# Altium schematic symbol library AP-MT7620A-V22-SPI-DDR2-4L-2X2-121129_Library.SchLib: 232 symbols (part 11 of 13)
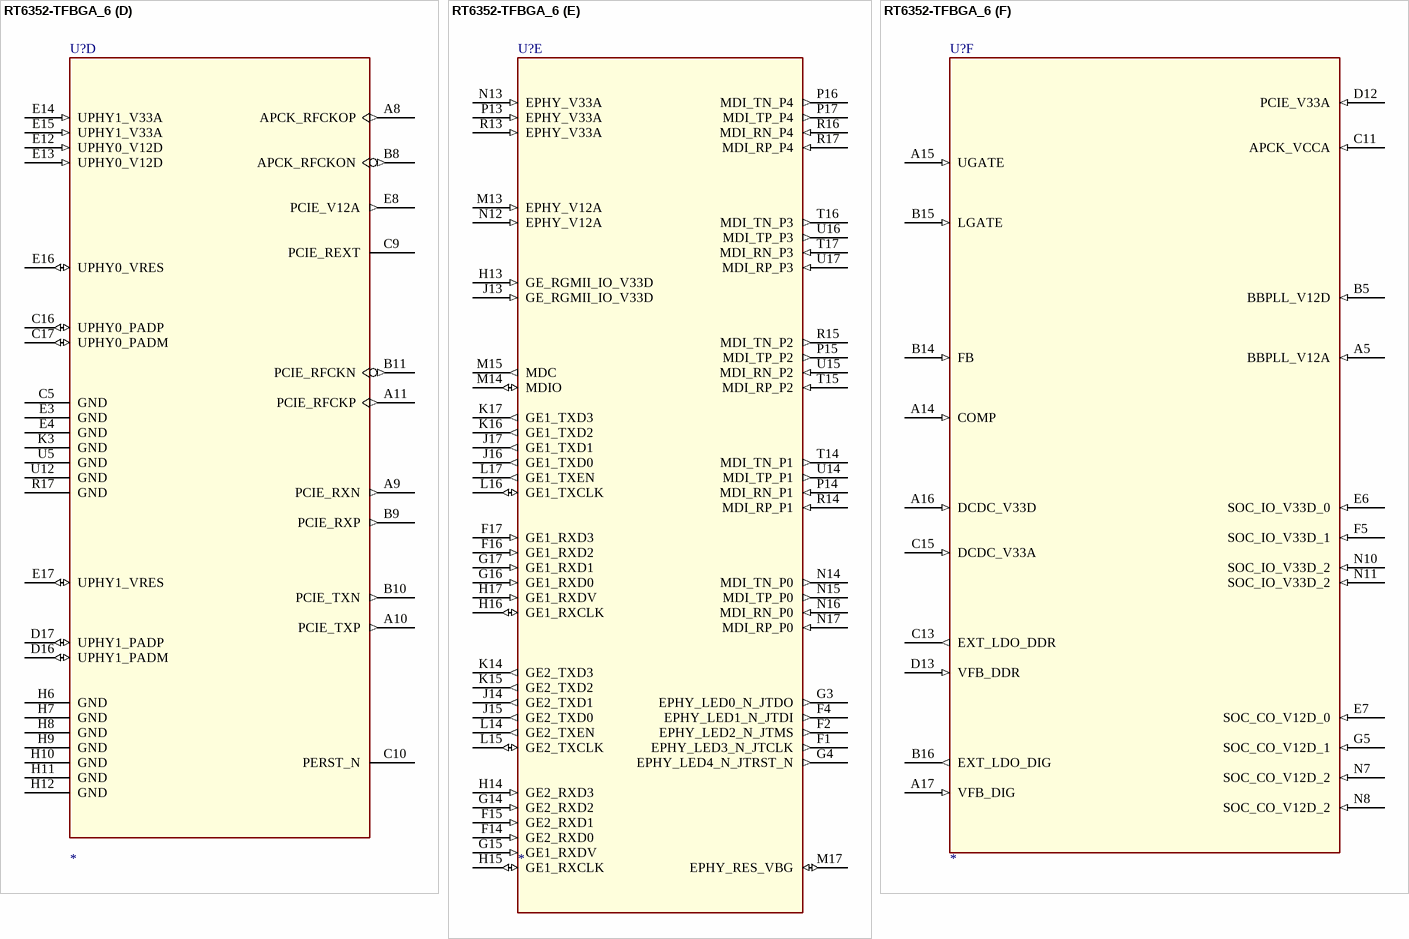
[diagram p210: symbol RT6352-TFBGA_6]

## RT6352-TFBGA_6
designator U?
footprint RT6352/BGA289/P0.65/12X12
part A pins: A1 RF0_PA2_V33P (in), A2 RF0_OUTP (out), A3 PLL_VC_CAP (out), A4 XTAL_XO (out), A6 ANT_TRN (out), B1 RF0_PA2_V33N (in), B2 RF0_OUTN (out), B3 PLL_VX_LDO, B4 XTAL_XI (out), B6 ANT_TRNB (out), C1 RF0_PA1_V33A (in), C2 RF1_VX_LDO, C3 RF0_VX_LDO, C4 XTAL_V12A (out), C6 PA_PE_G0 (out), D1 RF1_PA2_V33P (in), D2 RF1_PA2_V33N (in), D3 RF1_PA1_V33A (in), D4 BG_EXTR (out), D5 BG_V33A, D6 PA_PE_G1 (out), E1 RF1_OUTP (out), E2 RF1_OUTN (out), F3 WLED_N (out)
part B pins: F6 GND (power), F7 GND (power), F8 GND (power), F9 GND (power), F10 GND (power), F11 GND (power), F12 GND (power), G1 MD14 / MD15 (io), G2 MD9 / MD14 (io), G6 GND (power), G7 GND (power), G8 GND (power), G9 GND (power), G10 GND (power), G11 GND (power), G12 GND (power), H1 MD12 / MD13 (io), H2 MD11 / MD12 (io), H3 MRAS_N / MA5 (io), H4 MODT / MA4 (io), H5 DDR_IO_V18D/DDR_IO_V25D (in), J1 MD10 / MD11 (io), J2 MD13 / MD10 (io), J3 MCAS_N / MA7 (io), J4 MCS_N / MA6 (io), J5 DDR_IO_V18D/DDR_IO_V25D (in), K1 MD8 / MD9 (io), K2 MD15 / MD8 (io), K3 MA0 / MA8 (io), K4 MA2 / MA9 (io), K5 DDR_IOC_V12D (in), L1 MDQS1 (in), L2 MDQM1 (io), L3 MA6 / MA12 (io), L4 MA4 / MA11 (io), L5 DDR_IOC_V12D (in), M1 MCK_N (io), M2 MCK_P (io), M3 MA8 / MCKE (io), M5 MA11 / MODT (io), N1 MD5 / MD0 (io), N2 MD2 / MD1 (io), N3 MA9 / MA3 (io), N4 DDR_IO_VREF (in), N5 DDR_IO_V18D/DDR_IO_V25D (in), N6 DDR_IO_V18D/DDR_IO_V25D (in), P1 MD0 / MD2 (io), P2 MD7 / MD3 (io), P3 MA12 / MA2 (io), P4 MA7 / MA1 (io), P5 DDR_IO_VREF (in), R1 MD6 /MD4 (io), R2 MD1 / MD5 (io), R3 MA5 / MA0 (io), R4 MA3 / MA10 (io), T1 MD4 / MD6 (io), T2 MD3 / MD7 (io), T3 MA1 / MBA1 (io), T4 MBA0 / MCS_N (io), T5 MWE_N / MCAS_N (io), U1 MDQS0 (io), U2 MDQM0 (io), U3 MA10 / MBA0 (io), U4 MBA1 / MRAS_N (io), U5 MCKE / MWE_N (io)
part C pins: A7 SPI_CS0 (out), B7 SPI_CS1 (out), B17 PORST_N (in), C7 WDT_RST_N (out), C8 SPI_HOLD (out), D7 GPIO0 (io), D8 SPI_WP (out), D9 SPI_MISO (in), D10 SPI_MOSI (out), D11 SPI_CLK (out), J6 GND (power), J7 GND (power), J8 GND (power), J9 GND (power), J10 GND (power), J11 GND (power), J12 GND (power), K6 GND (power), K7 GND (power), K8 GND (power), K9 GND (power), K10 GND (power), K11 GND (power), K12 GND (power), L6 GND (power), L7 GND (power), L8 GND (power), L9 GND (power), L10 GND (power), L11 GND (power), L12 GND (power), M6 GND (power), M7 GND (power), M8 GND (power), M9 GND (power), M10 GND (power), M11 GND (power), M12 GND (power), P6 TXD2 (out), P7 RTS_N (out), P8 ND_D3/SD_D3 (out), P9 ND_D2/SD_D2 (out), P10 ND_D1/SD_D1 (out), P11 DSR_N (io), P12 RXD (io), R6 RXD2 (in), R7 ND_D5/bt_aux (out), R8 ND_CS_N (out), R9 ND_WP/SD_WP (out), R10 ND_D0/SD_D0 (out), R11 DCD_N (io), R12 RIN (io), T6 I2C_SD (out), T7 ND_D6/bt_wact (out), T8 ND_CLE/SD_card_detect, T9 ND_WE_N (out), T10 ND_ALE/SD_CMD (out), T11 TXD (out), T12 CTS_N (io), U6 I2C_SCLK (io), U7 ND_D7/bt_ant (out), U8 ND_D4/bt_stat (out), U9 ND_RE_N (out), U10 ND_RB_N/SD_CLK (out), U11 DTR_N (out)
part D pins: A8 APCK_RFCKOP (out), A9 PCIE_RXN (out), A10 PCIE_TXP (out), A11 PCIE_RFCKP (out), B8 APCK_RFCKON (out), B9 PCIE_RXP (out), B10 PCIE_TXN (out), B11 PCIE_RFCKN (out), C5 GND (power), C9 PCIE_REXT, C10 PERST_N, C16 UPHY0_PADP (io), C17 UPHY0_PADM (io), D16 UPHY1_PADM (io), D17 UPHY1_PADP (io), E3 GND (power), E4 GND (power), E8 PCIE_V12A (out), E12 UPHY0_V12D (in), E13 UPHY0_V12D (in), E14 UPHY1_V33A (in), E15 UPHY1_V33A (in), E16 UPHY0_VRES (io), E17 UPHY1_VRES (io), H6 GND (power), H7 GND (power), H8 GND (power), H9 GND (power), H10 GND (power), H11 GND (power), H12 GND (power), K3 GND (power), R17 GND (power), U5 GND (power), U12 GND (power)
part E pins: F1 EPHY_LED3_N_JTCLK (out), F2 EPHY_LED2_N_JTMS (out), F4 EPHY_LED1_N_JTDI (out), F14 GE2_RXD0 (in), F15 GE2_RXD1 (in), F16 GE1_RXD2 (in), F17 GE1_RXD3 (in), G3 EPHY_LED0_N_JTDO (out), G4 EPHY_LED4_N_JTRST_N (out), G14 GE2_RXD2 (in), G15 GE1_RXDV (in), G16 GE1_RXD0 (in), G17 GE1_RXD1 (in), H13 GE_RGMII_IO_V33D (in), H14 GE2_RXD3 (in), H15 GE1_RXCLK (io), H16 GE1_RXCLK (io), H17 GE1_RXDV (in), J13 GE_RGMII_IO_V33D (in), J14 GE2_TXD1 (out), J15 GE2_TXD0 (out), J16 GE1_TXD0 (out), J17 GE1_TXD1 (out), K14 GE2_TXD3 (out), K15 GE2_TXD2 (out), K16 GE1_TXD2 (out), K17 GE1_TXD3 (out), L14 GE2_TXEN (out), L15 GE2_TXCLK (io), L16 GE1_TXCLK (io), L17 GE1_TXEN (out), M13 EPHY_V12A (in), M14 MDIO (io), M15 MDC (out), M17 EPHY_RES_VBG (io), N12 EPHY_V12A (in), N13 EPHY_V33A (in), N14 MDI_TN_P0 (out), N15 MDI_TP_P0 (out), N16 MDI_RN_P0 (in), N17 MDI_RP_P0 (in), P13 EPHY_V33A (in), P14 MDI_RN_P1 (in), P15 MDI_TP_P2 (out), P16 MDI_TN_P4 (out), P17 MDI_TP_P4 (out), R13 EPHY_V33A (in), R14 MDI_RP_P1 (in), R15 MDI_TN_P2 (out), R16 MDI_RN_P4 (in), R17 MDI_RP_P4 (in), T14 MDI_TN_P1 (out), T15 MDI_RP_P2 (in), T16 MDI_TN_P3 (out), T17 MDI_RN_P3 (in), U14 MDI_TP_P1 (out), U15 MDI_RN_P2 (in), U16 MDI_TP_P3 (out), U17 MDI_RP_P3 (in)
part F pins: A5 BBPLL_V12A (in), A14 COMP (in), A15 UGATE (in), A16 DCDC_V33D (in), A17 VFB_DIG (in), B5 BBPLL_V12D (in), B14 FB (in), B15 LGATE (in), B16 EXT_LDO_DIG (out), C11 APCK_VCCA (in), C13 EXT_LDO_DDR (out), C15 DCDC_V33A (in), D12 PCIE_V33A (in), D13 VFB_DDR (in), E6 SOC_IO_V33D_0 (in), E7 SOC_CO_V12D_0 (in), F5 SOC_IO_V33D_1 (in), G5 SOC_CO_V12D_1 (in), N7 SOC_CO_V12D_2 (in), N8 SOC_CO_V12D_2 (in), N10 SOC_IO_V33D_2 (in), N11 SOC_IO_V33D_2 (in)

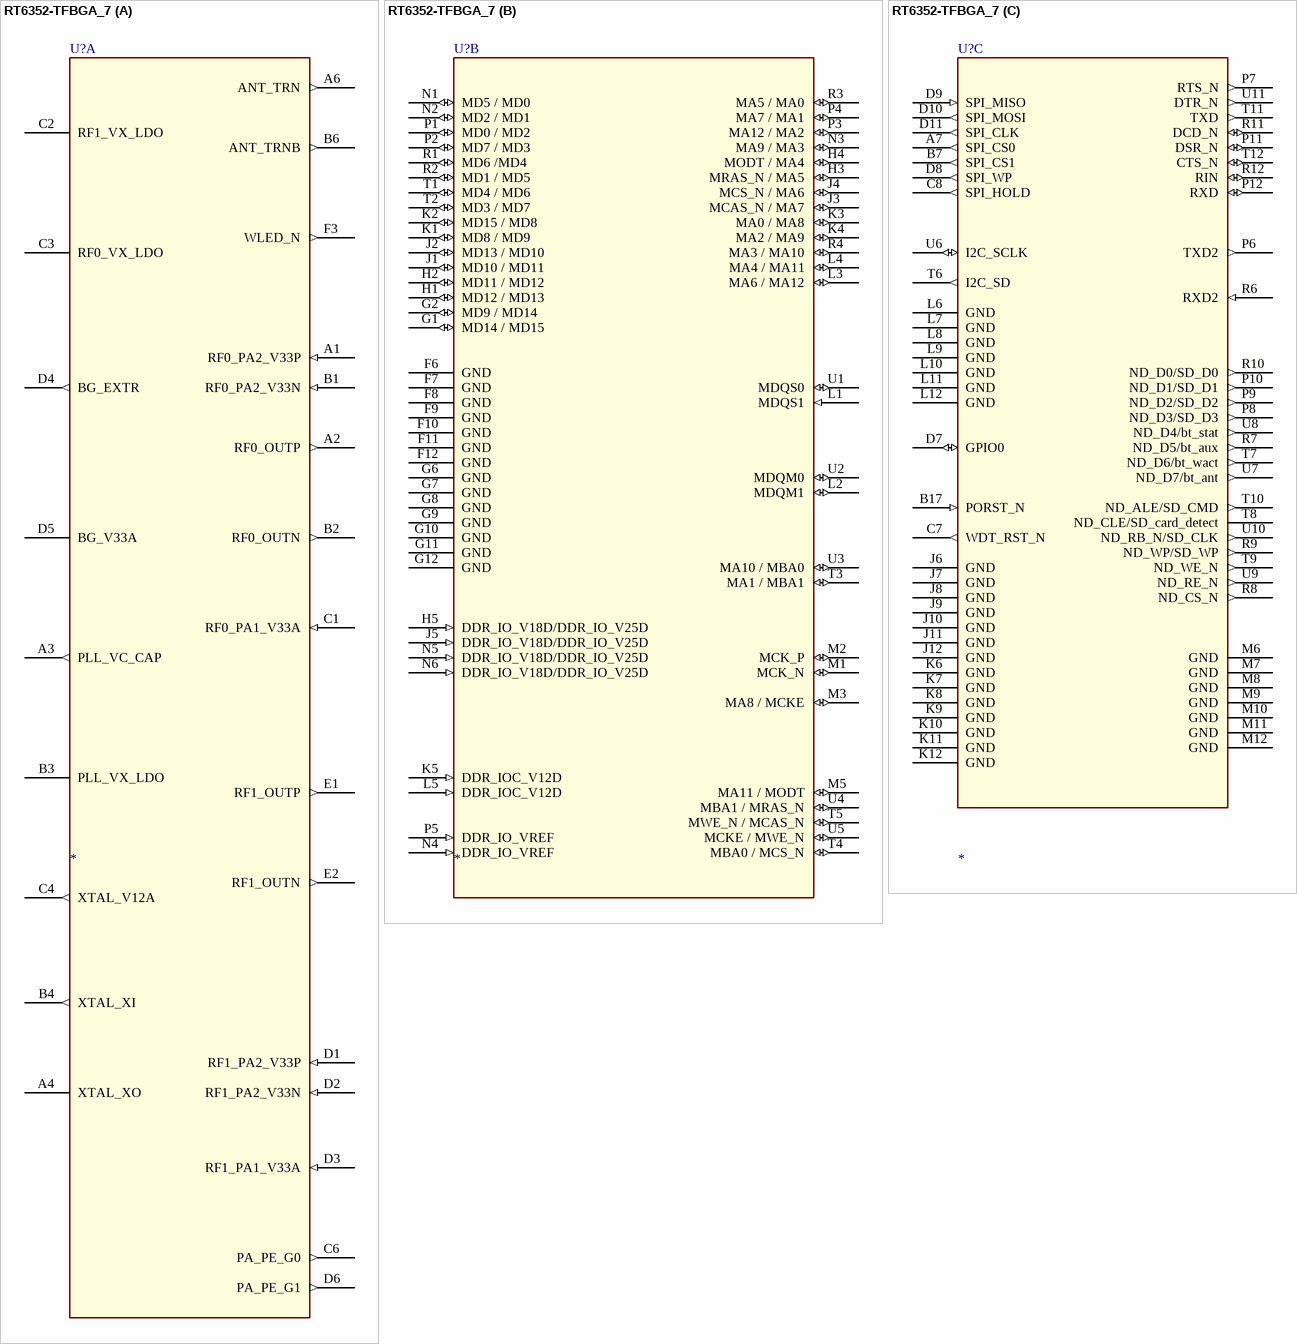
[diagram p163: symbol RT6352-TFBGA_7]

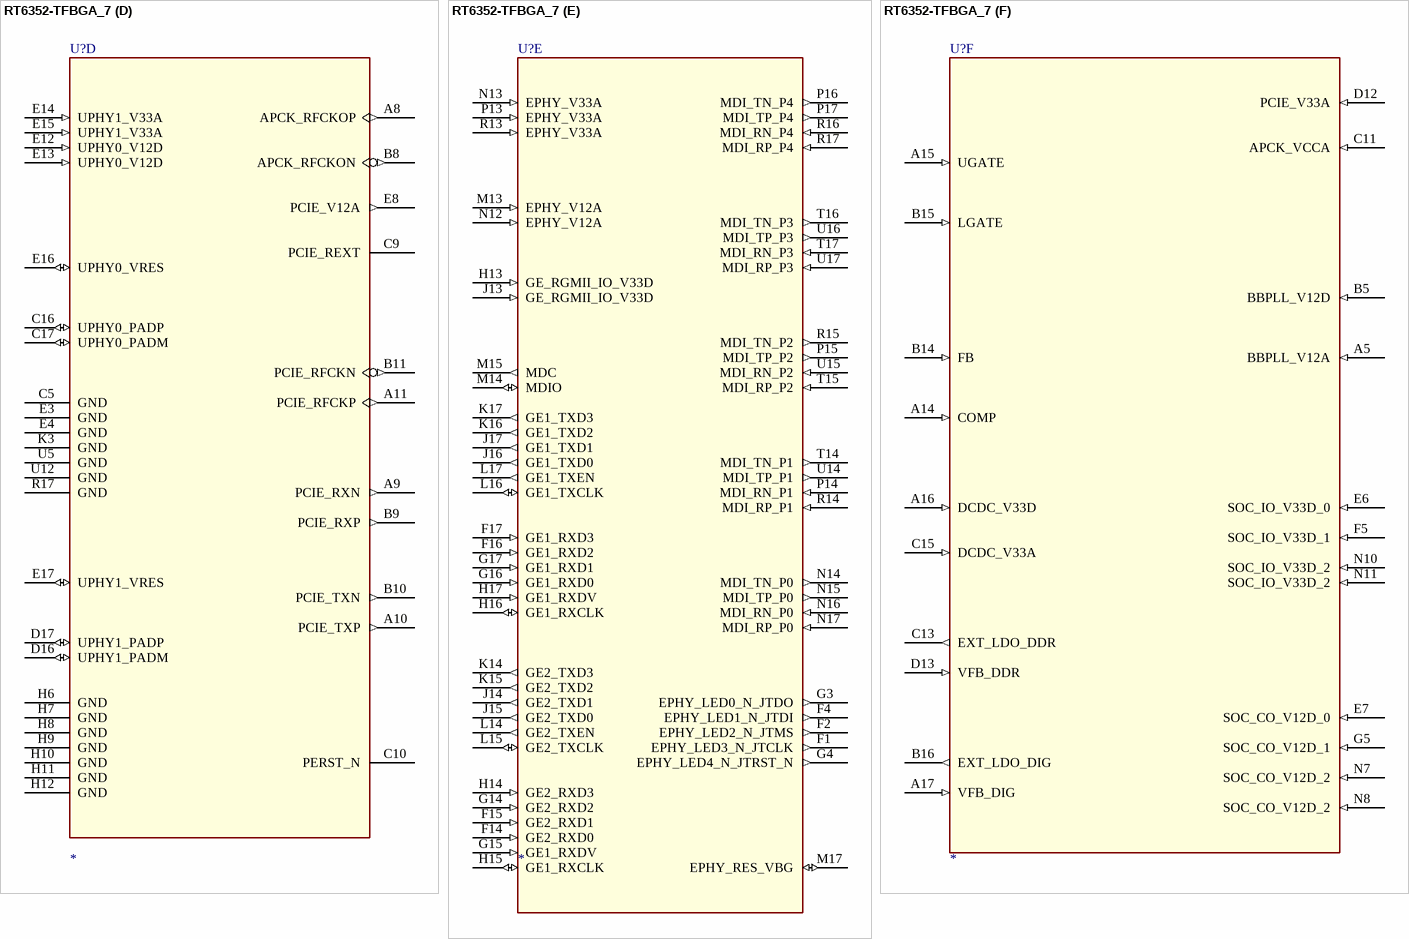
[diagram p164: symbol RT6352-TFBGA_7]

## RT6352-TFBGA_7
designator U?
footprint RT6352/BGA289/P0.65/12X12
part A pins: A1 RF0_PA2_V33P (in), A2 RF0_OUTP (out), A3 PLL_VC_CAP (out), A4 XTAL_XO, A6 ANT_TRN (out), B1 RF0_PA2_V33N (in), B2 RF0_OUTN (out), B3 PLL_VX_LDO, B4 XTAL_XI (out), B6 ANT_TRNB (out), C1 RF0_PA1_V33A (in), C2 RF1_VX_LDO, C3 RF0_VX_LDO, C4 XTAL_V12A (out), C6 PA_PE_G0 (out), D1 RF1_PA2_V33P (in), D2 RF1_PA2_V33N (in), D3 RF1_PA1_V33A (in), D4 BG_EXTR (out), D5 BG_V33A, D6 PA_PE_G1 (out), E1 RF1_OUTP (out), E2 RF1_OUTN (out), F3 WLED_N (out)
part B pins: F6 GND (power), F7 GND (power), F8 GND (power), F9 GND (power), F10 GND (power), F11 GND (power), F12 GND (power), G1 MD14 / MD15 (io), G2 MD9 / MD14 (io), G6 GND (power), G7 GND (power), G8 GND (power), G9 GND (power), G10 GND (power), G11 GND (power), G12 GND (power), H1 MD12 / MD13 (io), H2 MD11 / MD12 (io), H3 MRAS_N / MA5 (io), H4 MODT / MA4 (io), H5 DDR_IO_V18D/DDR_IO_V25D (in), J1 MD10 / MD11 (io), J2 MD13 / MD10 (io), J3 MCAS_N / MA7 (io), J4 MCS_N / MA6 (io), J5 DDR_IO_V18D/DDR_IO_V25D (in), K1 MD8 / MD9 (io), K2 MD15 / MD8 (io), K3 MA0 / MA8 (io), K4 MA2 / MA9 (io), K5 DDR_IOC_V12D (in), L1 MDQS1 (in), L2 MDQM1 (io), L3 MA6 / MA12 (io), L4 MA4 / MA11 (io), L5 DDR_IOC_V12D (in), M1 MCK_N (io), M2 MCK_P (io), M3 MA8 / MCKE (io), M5 MA11 / MODT (io), N1 MD5 / MD0 (io), N2 MD2 / MD1 (io), N3 MA9 / MA3 (io), N4 DDR_IO_VREF (in), N5 DDR_IO_V18D/DDR_IO_V25D (in), N6 DDR_IO_V18D/DDR_IO_V25D (in), P1 MD0 / MD2 (io), P2 MD7 / MD3 (io), P3 MA12 / MA2 (io), P4 MA7 / MA1 (io), P5 DDR_IO_VREF (in), R1 MD6 /MD4 (io), R2 MD1 / MD5 (io), R3 MA5 / MA0 (io), R4 MA3 / MA10 (io), T1 MD4 / MD6 (io), T2 MD3 / MD7 (io), T3 MA1 / MBA1 (io), T4 MBA0 / MCS_N (io), T5 MWE_N / MCAS_N (io), U1 MDQS0 (io), U2 MDQM0 (io), U3 MA10 / MBA0 (io), U4 MBA1 / MRAS_N (io), U5 MCKE / MWE_N (io)
part C pins: A7 SPI_CS0 (out), B7 SPI_CS1 (out), B17 PORST_N (in), C7 WDT_RST_N (out), C8 SPI_HOLD (out), D7 GPIO0 (io), D8 SPI_WP (out), D9 SPI_MISO (in), D10 SPI_MOSI (out), D11 SPI_CLK (out), J6 GND (power), J7 GND (power), J8 GND (power), J9 GND (power), J10 GND (power), J11 GND (power), J12 GND (power), K6 GND (power), K7 GND (power), K8 GND (power), K9 GND (power), K10 GND (power), K11 GND (power), K12 GND (power), L6 GND (power), L7 GND (power), L8 GND (power), L9 GND (power), L10 GND (power), L11 GND (power), L12 GND (power), M6 GND (power), M7 GND (power), M8 GND (power), M9 GND (power), M10 GND (power), M11 GND (power), M12 GND (power), P6 TXD2 (out), P7 RTS_N (out), P8 ND_D3/SD_D3 (out), P9 ND_D2/SD_D2 (out), P10 ND_D1/SD_D1 (out), P11 DSR_N (io), P12 RXD (io), R6 RXD2 (in), R7 ND_D5/bt_aux (out), R8 ND_CS_N (out), R9 ND_WP/SD_WP (out), R10 ND_D0/SD_D0 (out), R11 DCD_N (io), R12 RIN (io), T6 I2C_SD (out), T7 ND_D6/bt_wact (out), T8 ND_CLE/SD_card_detect, T9 ND_WE_N (out), T10 ND_ALE/SD_CMD (out), T11 TXD (out), T12 CTS_N (io), U6 I2C_SCLK (io), U7 ND_D7/bt_ant (out), U8 ND_D4/bt_stat (out), U9 ND_RE_N (out), U10 ND_RB_N/SD_CLK (out), U11 DTR_N (out)
part D pins: A8 APCK_RFCKOP (out), A9 PCIE_RXN (out), A10 PCIE_TXP (out), A11 PCIE_RFCKP (out), B8 APCK_RFCKON (out), B9 PCIE_RXP (out), B10 PCIE_TXN (out), B11 PCIE_RFCKN (out), C5 GND (power), C9 PCIE_REXT, C10 PERST_N, C16 UPHY0_PADP (io), C17 UPHY0_PADM (io), D16 UPHY1_PADM (io), D17 UPHY1_PADP (io), E3 GND (power), E4 GND (power), E8 PCIE_V12A (out), E12 UPHY0_V12D (in), E13 UPHY0_V12D (in), E14 UPHY1_V33A (in), E15 UPHY1_V33A (in), E16 UPHY0_VRES (io), E17 UPHY1_VRES (io), H6 GND (power), H7 GND (power), H8 GND (power), H9 GND (power), H10 GND (power), H11 GND (power), H12 GND (power), K3 GND (power), R17 GND (power), U5 GND (power), U12 GND (power)
part E pins: F1 EPHY_LED3_N_JTCLK (out), F2 EPHY_LED2_N_JTMS (out), F4 EPHY_LED1_N_JTDI (out), F14 GE2_RXD0 (in), F15 GE2_RXD1 (in), F16 GE1_RXD2 (in), F17 GE1_RXD3 (in), G3 EPHY_LED0_N_JTDO (out), G4 EPHY_LED4_N_JTRST_N (out), G14 GE2_RXD2 (in), G15 GE1_RXDV (in), G16 GE1_RXD0 (in), G17 GE1_RXD1 (in), H13 GE_RGMII_IO_V33D (in), H14 GE2_RXD3 (in), H15 GE1_RXCLK (io), H16 GE1_RXCLK (io), H17 GE1_RXDV (in), J13 GE_RGMII_IO_V33D (in), J14 GE2_TXD1 (out), J15 GE2_TXD0 (out), J16 GE1_TXD0 (out), J17 GE1_TXD1 (out), K14 GE2_TXD3 (out), K15 GE2_TXD2 (out), K16 GE1_TXD2 (out), K17 GE1_TXD3 (out), L14 GE2_TXEN (out), L15 GE2_TXCLK (io), L16 GE1_TXCLK (io), L17 GE1_TXEN (out), M13 EPHY_V12A (in), M14 MDIO (io), M15 MDC (out), M17 EPHY_RES_VBG (io), N12 EPHY_V12A (in), N13 EPHY_V33A (in), N14 MDI_TN_P0 (out), N15 MDI_TP_P0 (out), N16 MDI_RN_P0 (in), N17 MDI_RP_P0 (in), P13 EPHY_V33A (in), P14 MDI_RN_P1 (in), P15 MDI_TP_P2 (out), P16 MDI_TN_P4 (out), P17 MDI_TP_P4 (out), R13 EPHY_V33A (in), R14 MDI_RP_P1 (in), R15 MDI_TN_P2 (out), R16 MDI_RN_P4 (in), R17 MDI_RP_P4 (in), T14 MDI_TN_P1 (out), T15 MDI_RP_P2 (in), T16 MDI_TN_P3 (out), T17 MDI_RN_P3 (in), U14 MDI_TP_P1 (out), U15 MDI_RN_P2 (in), U16 MDI_TP_P3 (out), U17 MDI_RP_P3 (in)
part F pins: A5 BBPLL_V12A (in), A14 COMP (in), A15 UGATE (in), A16 DCDC_V33D (in), A17 VFB_DIG (in), B5 BBPLL_V12D (in), B14 FB (in), B15 LGATE (in), B16 EXT_LDO_DIG (out), C11 APCK_VCCA (in), C13 EXT_LDO_DDR (out), C15 DCDC_V33A (in), D12 PCIE_V33A (in), D13 VFB_DDR (in), E6 SOC_IO_V33D_0 (in), E7 SOC_CO_V12D_0 (in), F5 SOC_IO_V33D_1 (in), G5 SOC_CO_V12D_1 (in), N7 SOC_CO_V12D_2 (in), N8 SOC_CO_V12D_2 (in), N10 SOC_IO_V33D_2 (in), N11 SOC_IO_V33D_2 (in)

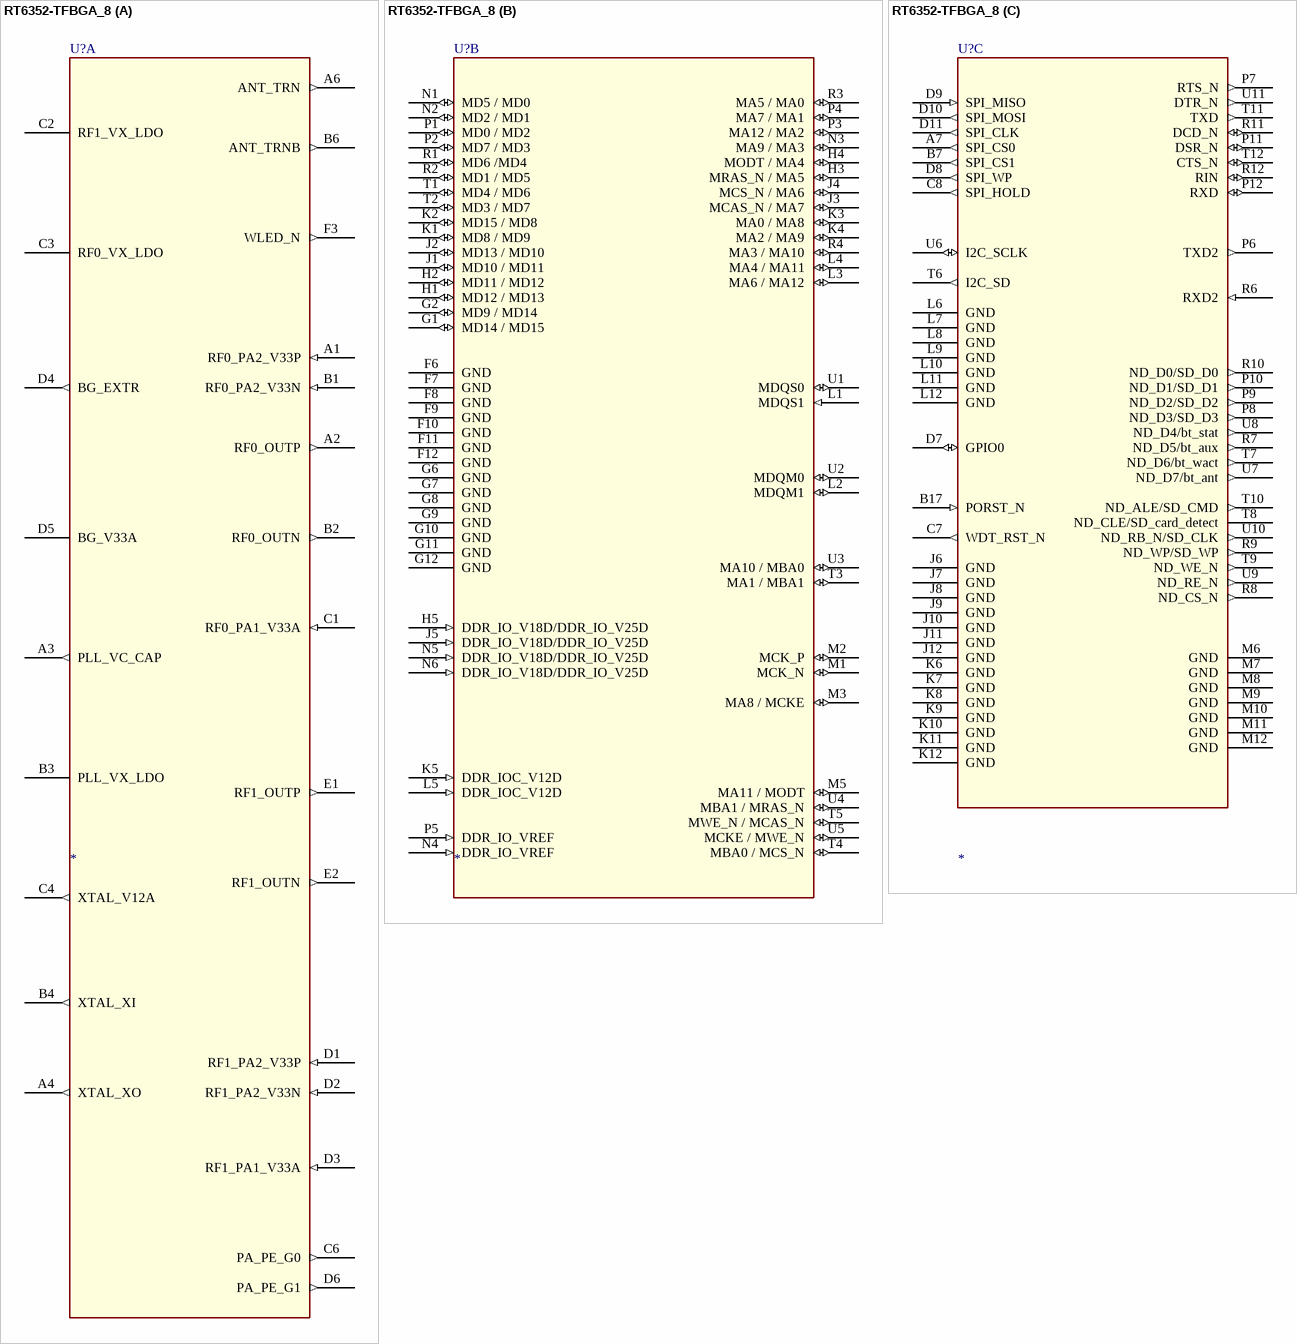
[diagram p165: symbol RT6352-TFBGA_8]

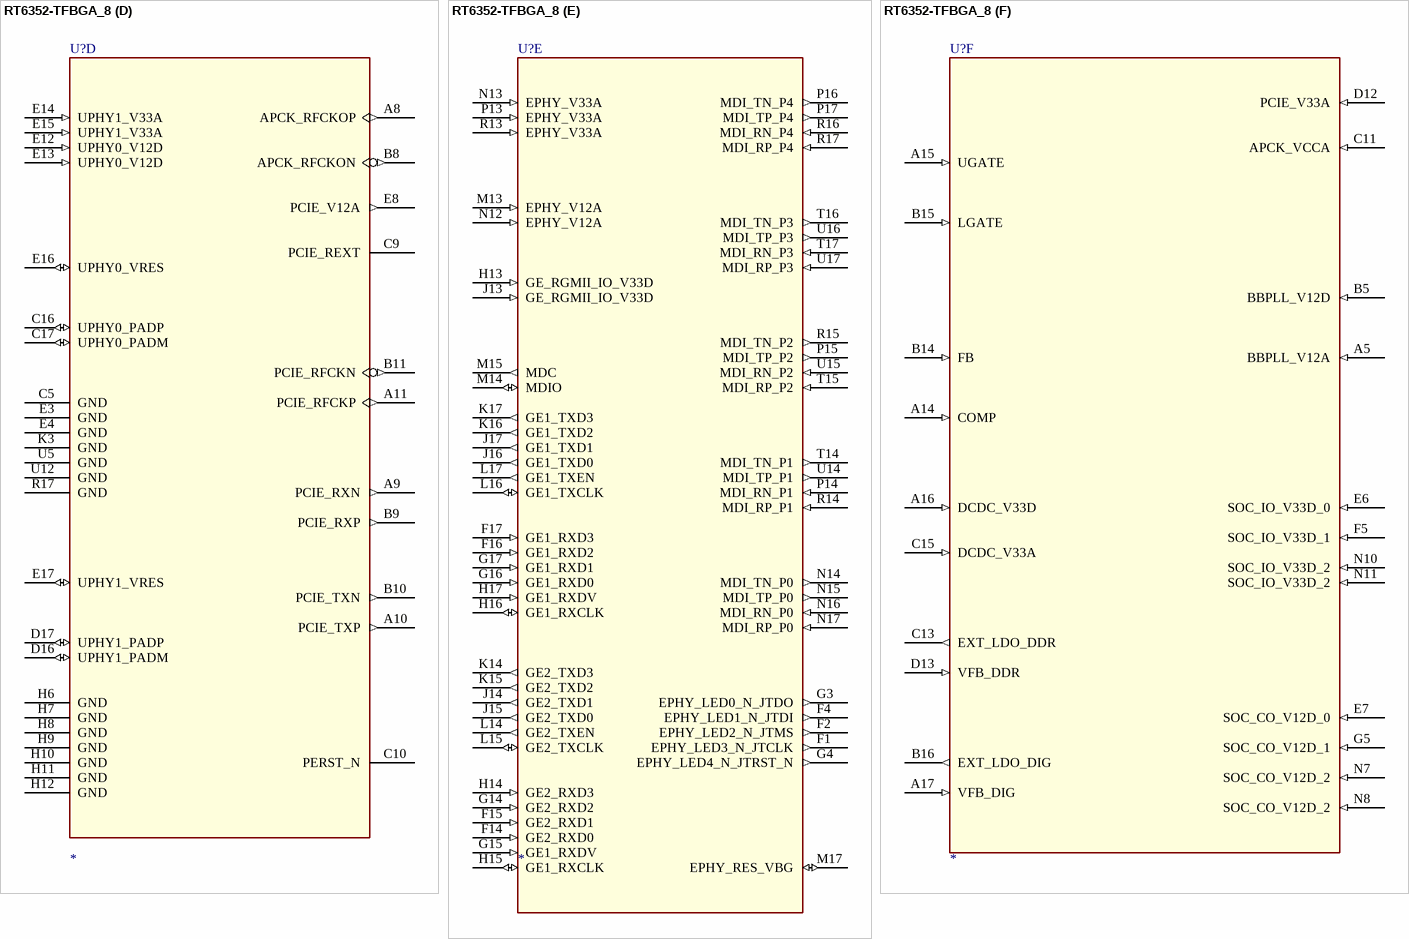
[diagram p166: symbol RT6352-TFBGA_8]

## RT6352-TFBGA_8
designator U?
footprint RT6352/BGA289/P0.65/12X12
part A pins: A1 RF0_PA2_V33P (in), A2 RF0_OUTP (out), A3 PLL_VC_CAP (out), A4 XTAL_XO (out), A6 ANT_TRN (out), B1 RF0_PA2_V33N (in), B2 RF0_OUTN (out), B3 PLL_VX_LDO, B4 XTAL_XI (out), B6 ANT_TRNB (out), C1 RF0_PA1_V33A (in), C2 RF1_VX_LDO, C3 RF0_VX_LDO, C4 XTAL_V12A (out), C6 PA_PE_G0 (out), D1 RF1_PA2_V33P (in), D2 RF1_PA2_V33N (in), D3 RF1_PA1_V33A (in), D4 BG_EXTR (out), D5 BG_V33A, D6 PA_PE_G1 (out), E1 RF1_OUTP (out), E2 RF1_OUTN (out), F3 WLED_N (out)
part B pins: F6 GND (power), F7 GND (power), F8 GND (power), F9 GND (power), F10 GND (power), F11 GND (power), F12 GND (power), G1 MD14 / MD15 (io), G2 MD9 / MD14 (io), G6 GND (power), G7 GND (power), G8 GND (power), G9 GND (power), G10 GND (power), G11 GND (power), G12 GND (power), H1 MD12 / MD13 (io), H2 MD11 / MD12 (io), H3 MRAS_N / MA5 (io), H4 MODT / MA4 (io), H5 DDR_IO_V18D/DDR_IO_V25D (in), J1 MD10 / MD11 (io), J2 MD13 / MD10 (io), J3 MCAS_N / MA7 (io), J4 MCS_N / MA6 (io), J5 DDR_IO_V18D/DDR_IO_V25D (in), K1 MD8 / MD9 (io), K2 MD15 / MD8 (io), K3 MA0 / MA8 (io), K4 MA2 / MA9 (io), K5 DDR_IOC_V12D (in), L1 MDQS1 (in), L2 MDQM1 (io), L3 MA6 / MA12 (io), L4 MA4 / MA11 (io), L5 DDR_IOC_V12D (in), M1 MCK_N (io), M2 MCK_P (io), M3 MA8 / MCKE (io), M5 MA11 / MODT (io), N1 MD5 / MD0 (io), N2 MD2 / MD1 (io), N3 MA9 / MA3 (io), N4 DDR_IO_VREF (in), N5 DDR_IO_V18D/DDR_IO_V25D (in), N6 DDR_IO_V18D/DDR_IO_V25D (in), P1 MD0 / MD2 (io), P2 MD7 / MD3 (io), P3 MA12 / MA2 (io), P4 MA7 / MA1 (io), P5 DDR_IO_VREF (in), R1 MD6 /MD4 (io), R2 MD1 / MD5 (io), R3 MA5 / MA0 (io), R4 MA3 / MA10 (io), T1 MD4 / MD6 (io), T2 MD3 / MD7 (io), T3 MA1 / MBA1 (io), T4 MBA0 / MCS_N (io), T5 MWE_N / MCAS_N (io), U1 MDQS0 (io), U2 MDQM0 (io), U3 MA10 / MBA0 (io), U4 MBA1 / MRAS_N (io), U5 MCKE / MWE_N (io)
part C pins: A7 SPI_CS0 (out), B7 SPI_CS1 (out), B17 PORST_N (in), C7 WDT_RST_N (out), C8 SPI_HOLD (out), D7 GPIO0 (io), D8 SPI_WP (out), D9 SPI_MISO (in), D10 SPI_MOSI (out), D11 SPI_CLK (out), J6 GND (power), J7 GND (power), J8 GND (power), J9 GND (power), J10 GND (power), J11 GND (power), J12 GND (power), K6 GND (power), K7 GND (power), K8 GND (power), K9 GND (power), K10 GND (power), K11 GND (power), K12 GND (power), L6 GND (power), L7 GND (power), L8 GND (power), L9 GND (power), L10 GND (power), L11 GND (power), L12 GND (power), M6 GND (power), M7 GND (power), M8 GND (power), M9 GND (power), M10 GND (power), M11 GND (power), M12 GND (power), P6 TXD2 (out), P7 RTS_N (out), P8 ND_D3/SD_D3 (out), P9 ND_D2/SD_D2 (out), P10 ND_D1/SD_D1 (out), P11 DSR_N (io), P12 RXD (io), R6 RXD2 (in), R7 ND_D5/bt_aux (out), R8 ND_CS_N (out), R9 ND_WP/SD_WP (out), R10 ND_D0/SD_D0 (out), R11 DCD_N (io), R12 RIN (io), T6 I2C_SD (out), T7 ND_D6/bt_wact (out), T8 ND_CLE/SD_card_detect, T9 ND_WE_N (out), T10 ND_ALE/SD_CMD (out), T11 TXD (out), T12 CTS_N (io), U6 I2C_SCLK (io), U7 ND_D7/bt_ant (out), U8 ND_D4/bt_stat (out), U9 ND_RE_N (out), U10 ND_RB_N/SD_CLK (out), U11 DTR_N (out)
part D pins: A8 APCK_RFCKOP (out), A9 PCIE_RXN (out), A10 PCIE_TXP (out), A11 PCIE_RFCKP (out), B8 APCK_RFCKON (out), B9 PCIE_RXP (out), B10 PCIE_TXN (out), B11 PCIE_RFCKN (out), C5 GND (power), C9 PCIE_REXT, C10 PERST_N, C16 UPHY0_PADP (io), C17 UPHY0_PADM (io), D16 UPHY1_PADM (io), D17 UPHY1_PADP (io), E3 GND (power), E4 GND (power), E8 PCIE_V12A (out), E12 UPHY0_V12D (in), E13 UPHY0_V12D (in), E14 UPHY1_V33A (in), E15 UPHY1_V33A (in), E16 UPHY0_VRES (io), E17 UPHY1_VRES (io), H6 GND (power), H7 GND (power), H8 GND (power), H9 GND (power), H10 GND (power), H11 GND (power), H12 GND (power), K3 GND (power), R17 GND (power), U5 GND (power), U12 GND (power)
part E pins: F1 EPHY_LED3_N_JTCLK (out), F2 EPHY_LED2_N_JTMS (out), F4 EPHY_LED1_N_JTDI (out), F14 GE2_RXD0 (in), F15 GE2_RXD1 (in), F16 GE1_RXD2 (in), F17 GE1_RXD3 (in), G3 EPHY_LED0_N_JTDO (out), G4 EPHY_LED4_N_JTRST_N (out), G14 GE2_RXD2 (in), G15 GE1_RXDV (in), G16 GE1_RXD0 (in), G17 GE1_RXD1 (in), H13 GE_RGMII_IO_V33D (in), H14 GE2_RXD3 (in), H15 GE1_RXCLK (io), H16 GE1_RXCLK (io), H17 GE1_RXDV (in), J13 GE_RGMII_IO_V33D (in), J14 GE2_TXD1 (out), J15 GE2_TXD0 (out), J16 GE1_TXD0 (out), J17 GE1_TXD1 (out), K14 GE2_TXD3 (out), K15 GE2_TXD2 (out), K16 GE1_TXD2 (out), K17 GE1_TXD3 (out), L14 GE2_TXEN (out), L15 GE2_TXCLK (io), L16 GE1_TXCLK (io), L17 GE1_TXEN (out), M13 EPHY_V12A (in), M14 MDIO (io), M15 MDC (out), M17 EPHY_RES_VBG (io), N12 EPHY_V12A (in), N13 EPHY_V33A (in), N14 MDI_TN_P0 (out), N15 MDI_TP_P0 (out), N16 MDI_RN_P0 (in), N17 MDI_RP_P0 (in), P13 EPHY_V33A (in), P14 MDI_RN_P1 (in), P15 MDI_TP_P2 (out), P16 MDI_TN_P4 (out), P17 MDI_TP_P4 (out), R13 EPHY_V33A (in), R14 MDI_RP_P1 (in), R15 MDI_TN_P2 (out), R16 MDI_RN_P4 (in), R17 MDI_RP_P4 (in), T14 MDI_TN_P1 (out), T15 MDI_RP_P2 (in), T16 MDI_TN_P3 (out), T17 MDI_RN_P3 (in), U14 MDI_TP_P1 (out), U15 MDI_RN_P2 (in), U16 MDI_TP_P3 (out), U17 MDI_RP_P3 (in)
part F pins: A5 BBPLL_V12A (in), A14 COMP (in), A15 UGATE (in), A16 DCDC_V33D (in), A17 VFB_DIG (in), B5 BBPLL_V12D (in), B14 FB (in), B15 LGATE (in), B16 EXT_LDO_DIG (out), C11 APCK_VCCA (in), C13 EXT_LDO_DDR (out), C15 DCDC_V33A (in), D12 PCIE_V33A (in), D13 VFB_DDR (in), E6 SOC_IO_V33D_0 (in), E7 SOC_CO_V12D_0 (in), F5 SOC_IO_V33D_1 (in), G5 SOC_CO_V12D_1 (in), N7 SOC_CO_V12D_2 (in), N8 SOC_CO_V12D_2 (in), N10 SOC_IO_V33D_2 (in), N11 SOC_IO_V33D_2 (in)

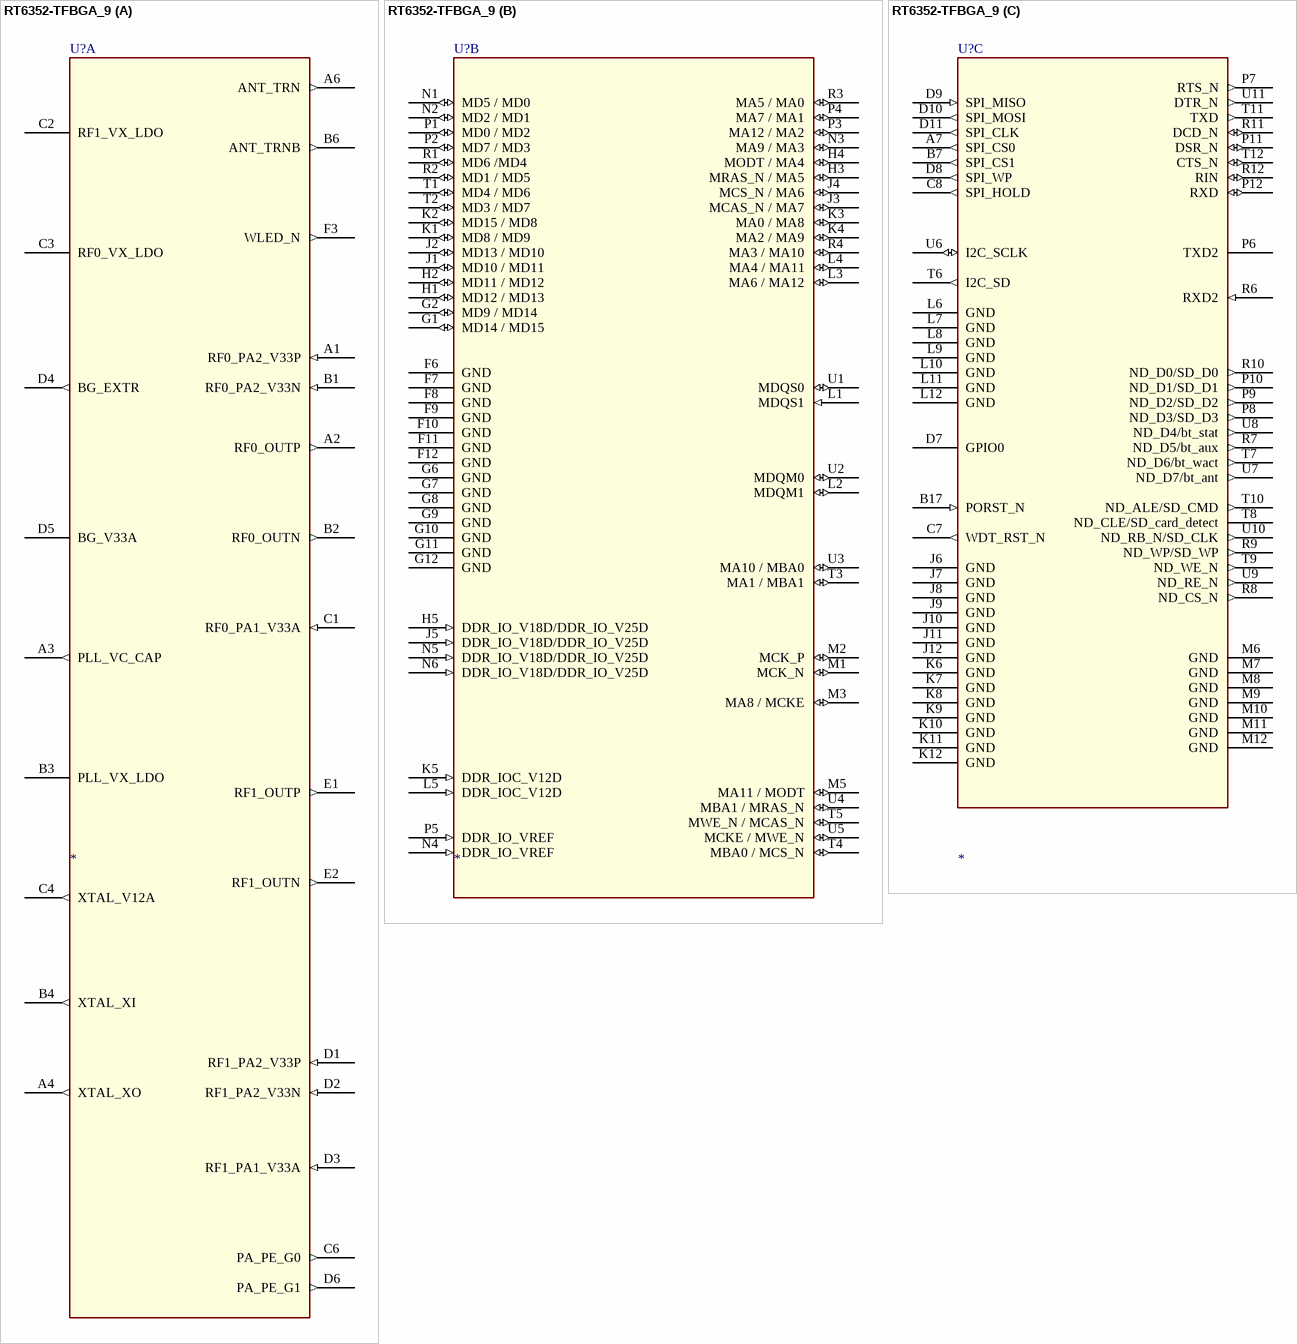
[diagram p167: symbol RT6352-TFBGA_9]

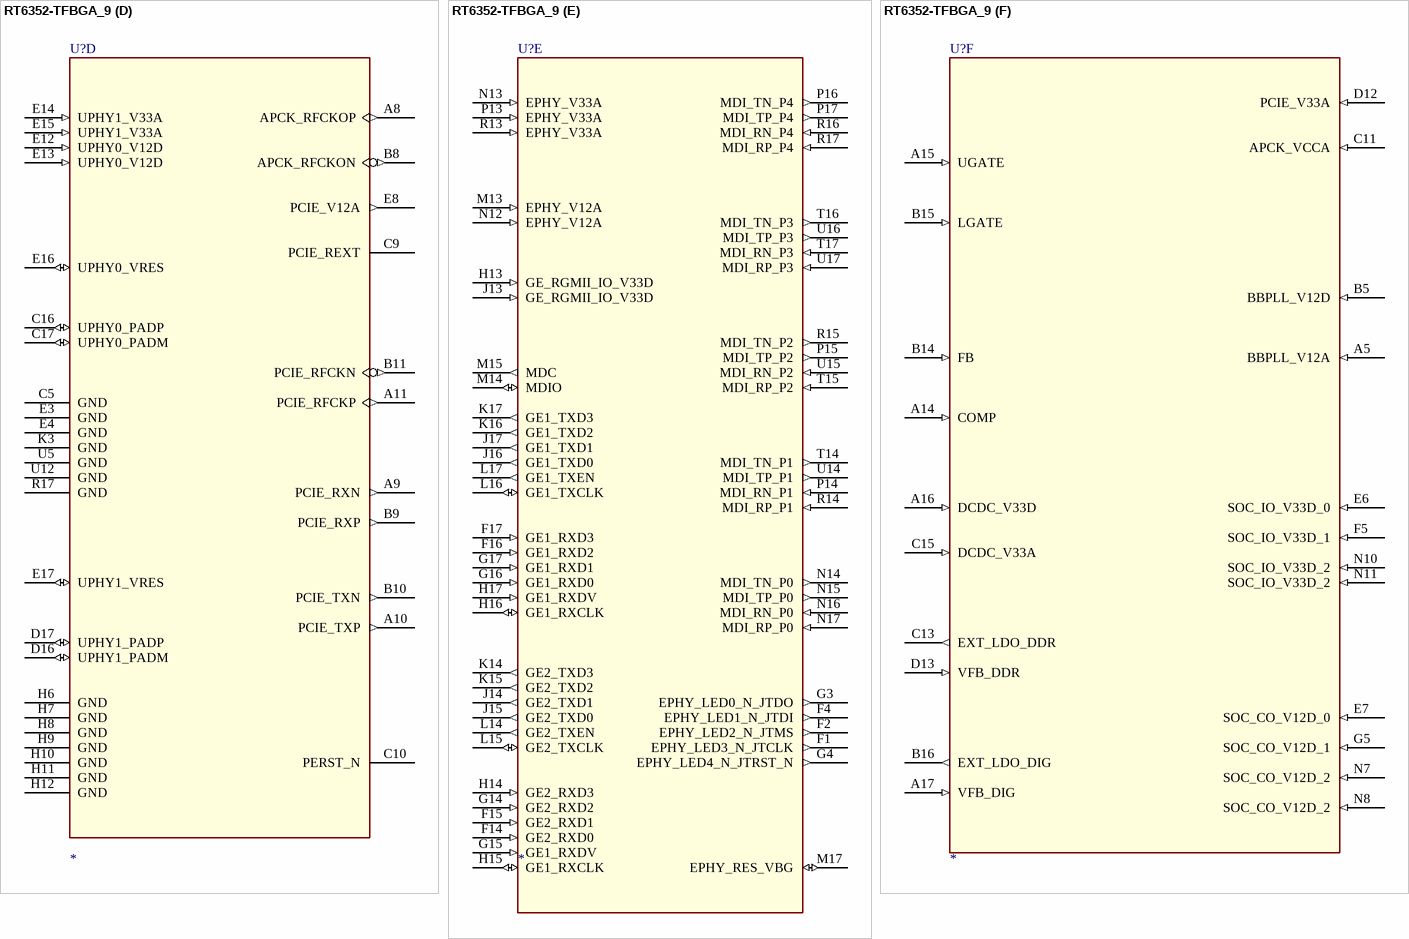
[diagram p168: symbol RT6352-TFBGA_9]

## RT6352-TFBGA_9
designator U?
footprint RT6352/BGA289/P0.65/12X12
part A pins: A1 RF0_PA2_V33P (in), A2 RF0_OUTP (out), A3 PLL_VC_CAP (out), A4 XTAL_XO (out), A6 ANT_TRN (out), B1 RF0_PA2_V33N (in), B2 RF0_OUTN (out), B3 PLL_VX_LDO, B4 XTAL_XI (out), B6 ANT_TRNB (out), C1 RF0_PA1_V33A (in), C2 RF1_VX_LDO, C3 RF0_VX_LDO, C4 XTAL_V12A (out), C6 PA_PE_G0 (out), D1 RF1_PA2_V33P (in), D2 RF1_PA2_V33N (in), D3 RF1_PA1_V33A (in), D4 BG_EXTR (out), D5 BG_V33A, D6 PA_PE_G1 (out), E1 RF1_OUTP (out), E2 RF1_OUTN (out), F3 WLED_N (out)
part B pins: F6 GND (power), F7 GND (power), F8 GND (power), F9 GND (power), F10 GND (power), F11 GND (power), F12 GND (power), G1 MD14 / MD15 (io), G2 MD9 / MD14 (io), G6 GND (power), G7 GND (power), G8 GND (power), G9 GND (power), G10 GND (power), G11 GND (power), G12 GND (power), H1 MD12 / MD13 (io), H2 MD11 / MD12 (io), H3 MRAS_N / MA5 (io), H4 MODT / MA4 (io), H5 DDR_IO_V18D/DDR_IO_V25D (in), J1 MD10 / MD11 (io), J2 MD13 / MD10 (io), J3 MCAS_N / MA7 (io), J4 MCS_N / MA6 (io), J5 DDR_IO_V18D/DDR_IO_V25D (in), K1 MD8 / MD9 (io), K2 MD15 / MD8 (io), K3 MA0 / MA8 (io), K4 MA2 / MA9 (io), K5 DDR_IOC_V12D (in), L1 MDQS1 (in), L2 MDQM1 (io), L3 MA6 / MA12 (io), L4 MA4 / MA11 (io), L5 DDR_IOC_V12D (in), M1 MCK_N (io), M2 MCK_P (io), M3 MA8 / MCKE (io), M5 MA11 / MODT (io), N1 MD5 / MD0 (io), N2 MD2 / MD1 (io), N3 MA9 / MA3 (io), N4 DDR_IO_VREF (in), N5 DDR_IO_V18D/DDR_IO_V25D (in), N6 DDR_IO_V18D/DDR_IO_V25D (in), P1 MD0 / MD2 (io), P2 MD7 / MD3 (io), P3 MA12 / MA2 (io), P4 MA7 / MA1 (io), P5 DDR_IO_VREF (in), R1 MD6 /MD4 (io), R2 MD1 / MD5 (io), R3 MA5 / MA0 (io), R4 MA3 / MA10 (io), T1 MD4 / MD6 (io), T2 MD3 / MD7 (io), T3 MA1 / MBA1 (io), T4 MBA0 / MCS_N (io), T5 MWE_N / MCAS_N (io), U1 MDQS0 (io), U2 MDQM0 (io), U3 MA10 / MBA0 (io), U4 MBA1 / MRAS_N (io), U5 MCKE / MWE_N (io)
part C pins: A7 SPI_CS0 (out), B7 SPI_CS1 (out), B17 PORST_N (in), C7 WDT_RST_N (out), C8 SPI_HOLD (out), D7 GPIO0, D8 SPI_WP (out), D9 SPI_MISO (in), D10 SPI_MOSI (out), D11 SPI_CLK (out), J6 GND (power), J7 GND (power), J8 GND (power), J9 GND (power), J10 GND (power), J11 GND (power), J12 GND (power), K6 GND (power), K7 GND (power), K8 GND (power), K9 GND (power), K10 GND (power), K11 GND (power), K12 GND (power), L6 GND (power), L7 GND (power), L8 GND (power), L9 GND (power), L10 GND (power), L11 GND (power), L12 GND (power), M6 GND (power), M7 GND (power), M8 GND (power), M9 GND (power), M10 GND (power), M11 GND (power), M12 GND (power), P6 TXD2, P7 RTS_N (out), P8 ND_D3/SD_D3 (out), P9 ND_D2/SD_D2 (out), P10 ND_D1/SD_D1 (out), P11 DSR_N (io), P12 RXD (io), R6 RXD2 (in), R7 ND_D5/bt_aux (out), R8 ND_CS_N (out), R9 ND_WP/SD_WP (out), R10 ND_D0/SD_D0 (out), R11 DCD_N (io), R12 RIN (io), T6 I2C_SD (out), T7 ND_D6/bt_wact (out), T8 ND_CLE/SD_card_detect, T9 ND_WE_N (out), T10 ND_ALE/SD_CMD (out), T11 TXD (out), T12 CTS_N (io), U6 I2C_SCLK (io), U7 ND_D7/bt_ant (out), U8 ND_D4/bt_stat (out), U9 ND_RE_N (out), U10 ND_RB_N/SD_CLK (out), U11 DTR_N (out)
part D pins: A8 APCK_RFCKOP (out), A9 PCIE_RXN (out), A10 PCIE_TXP (out), A11 PCIE_RFCKP (out), B8 APCK_RFCKON (out), B9 PCIE_RXP (out), B10 PCIE_TXN (out), B11 PCIE_RFCKN (out), C5 GND (power), C9 PCIE_REXT, C10 PERST_N, C16 UPHY0_PADP (io), C17 UPHY0_PADM (io), D16 UPHY1_PADM (io), D17 UPHY1_PADP (io), E3 GND (power), E4 GND (power), E8 PCIE_V12A (out), E12 UPHY0_V12D (in), E13 UPHY0_V12D (in), E14 UPHY1_V33A (in), E15 UPHY1_V33A (in), E16 UPHY0_VRES (io), E17 UPHY1_VRES (io), H6 GND (power), H7 GND (power), H8 GND (power), H9 GND (power), H10 GND (power), H11 GND (power), H12 GND (power), K3 GND (power), R17 GND (power), U5 GND (power), U12 GND (power)
part E pins: F1 EPHY_LED3_N_JTCLK (out), F2 EPHY_LED2_N_JTMS (out), F4 EPHY_LED1_N_JTDI (out), F14 GE2_RXD0 (in), F15 GE2_RXD1 (in), F16 GE1_RXD2 (in), F17 GE1_RXD3 (in), G3 EPHY_LED0_N_JTDO (out), G4 EPHY_LED4_N_JTRST_N (out), G14 GE2_RXD2 (in), G15 GE1_RXDV (in), G16 GE1_RXD0 (in), G17 GE1_RXD1 (in), H13 GE_RGMII_IO_V33D (in), H14 GE2_RXD3 (in), H15 GE1_RXCLK (io), H16 GE1_RXCLK (io), H17 GE1_RXDV (in), J13 GE_RGMII_IO_V33D (in), J14 GE2_TXD1 (out), J15 GE2_TXD0 (out), J16 GE1_TXD0 (out), J17 GE1_TXD1 (out), K14 GE2_TXD3 (out), K15 GE2_TXD2 (out), K16 GE1_TXD2 (out), K17 GE1_TXD3 (out), L14 GE2_TXEN (out), L15 GE2_TXCLK (io), L16 GE1_TXCLK (io), L17 GE1_TXEN (out), M13 EPHY_V12A (in), M14 MDIO (io), M15 MDC (out), M17 EPHY_RES_VBG (io), N12 EPHY_V12A (in), N13 EPHY_V33A (in), N14 MDI_TN_P0 (out), N15 MDI_TP_P0 (out), N16 MDI_RN_P0 (in), N17 MDI_RP_P0 (in), P13 EPHY_V33A (in), P14 MDI_RN_P1 (in), P15 MDI_TP_P2 (out), P16 MDI_TN_P4 (out), P17 MDI_TP_P4 (out), R13 EPHY_V33A (in), R14 MDI_RP_P1 (in), R15 MDI_TN_P2 (out), R16 MDI_RN_P4 (in), R17 MDI_RP_P4 (in), T14 MDI_TN_P1 (out), T15 MDI_RP_P2 (in), T16 MDI_TN_P3 (out), T17 MDI_RN_P3 (in), U14 MDI_TP_P1 (out), U15 MDI_RN_P2 (in), U16 MDI_TP_P3 (out), U17 MDI_RP_P3 (in)
part F pins: A5 BBPLL_V12A (in), A14 COMP (in), A15 UGATE (in), A16 DCDC_V33D (in), A17 VFB_DIG (in), B5 BBPLL_V12D (in), B14 FB (in), B15 LGATE (in), B16 EXT_LDO_DIG (out), C11 APCK_VCCA (in), C13 EXT_LDO_DDR (out), C15 DCDC_V33A (in), D12 PCIE_V33A (in), D13 VFB_DDR (in), E6 SOC_IO_V33D_0 (in), E7 SOC_CO_V12D_0 (in), F5 SOC_IO_V33D_1 (in), G5 SOC_CO_V12D_1 (in), N7 SOC_CO_V12D_2 (in), N8 SOC_CO_V12D_2 (in), N10 SOC_IO_V33D_2 (in), N11 SOC_IO_V33D_2 (in)

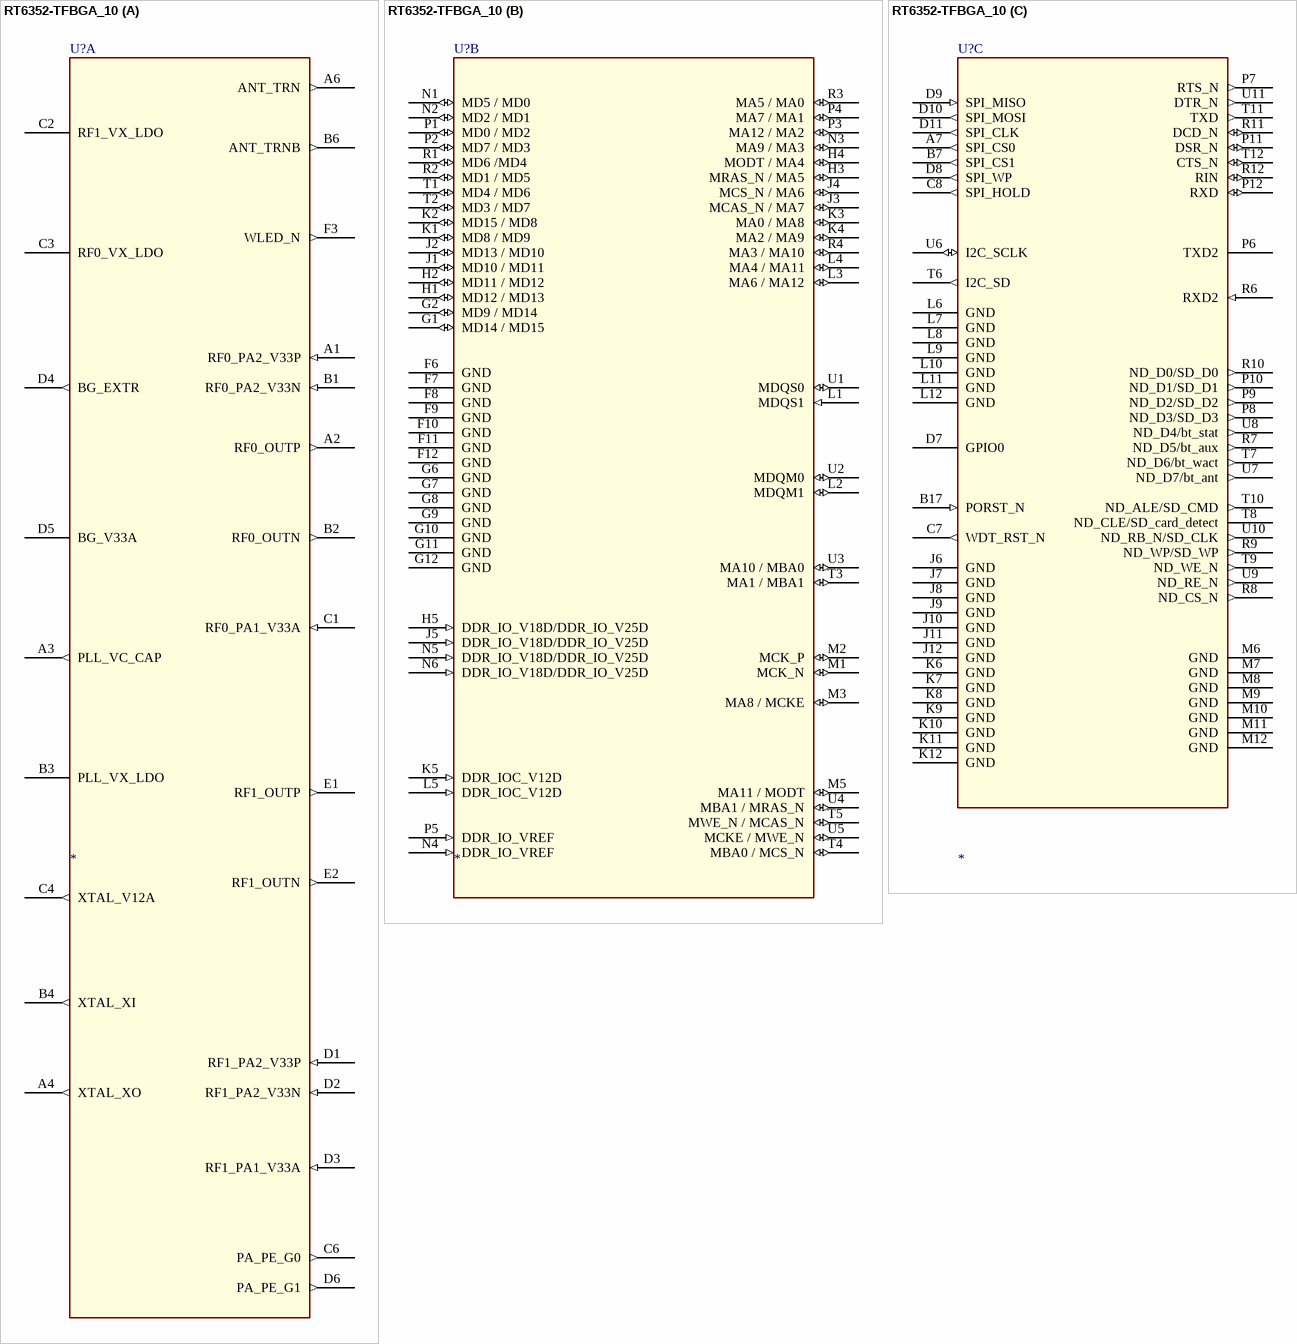
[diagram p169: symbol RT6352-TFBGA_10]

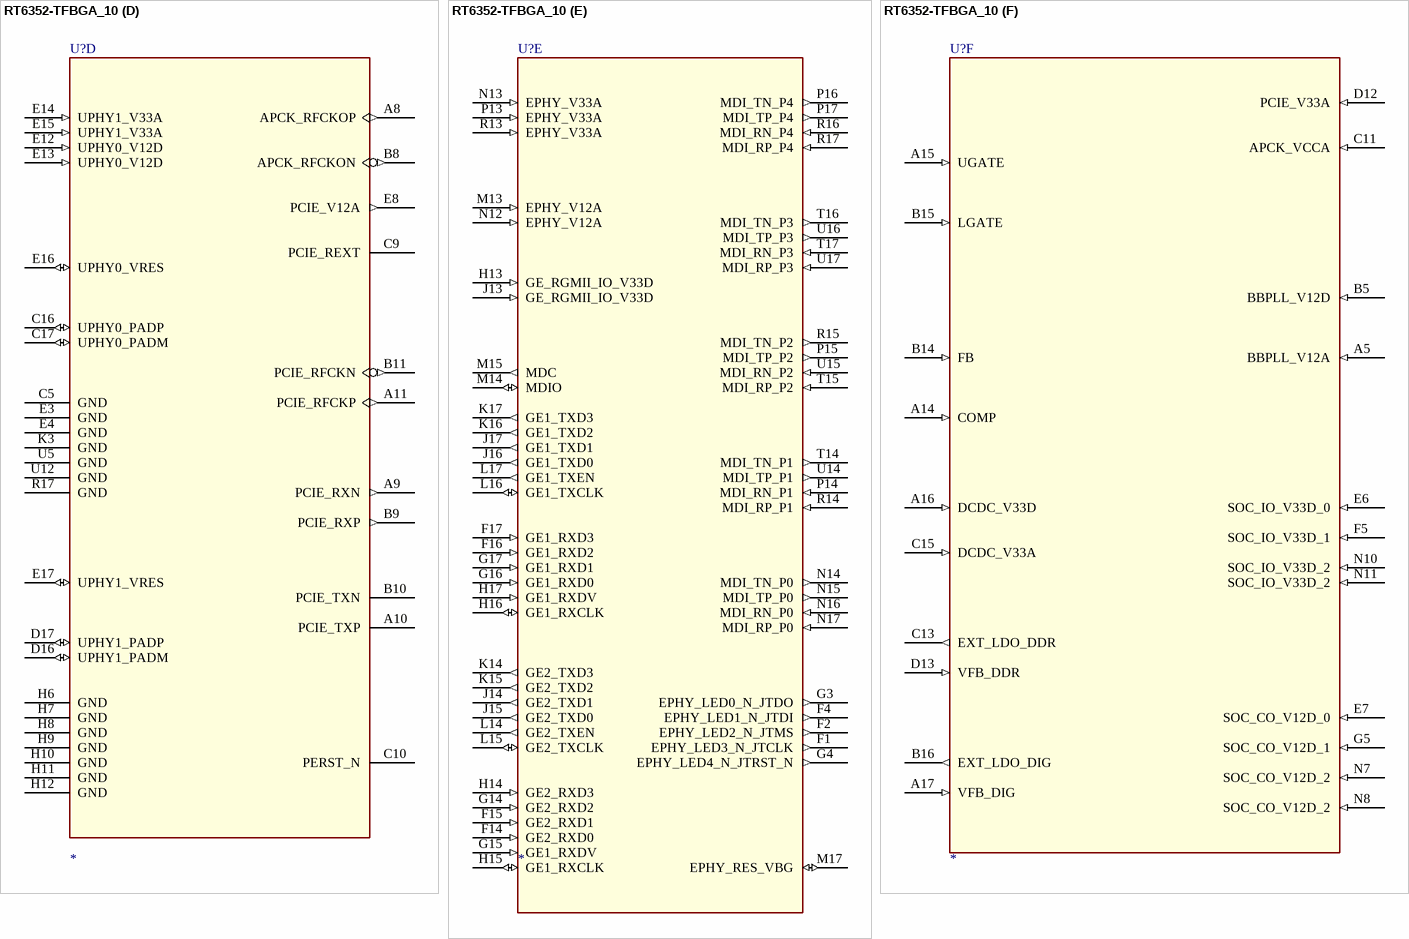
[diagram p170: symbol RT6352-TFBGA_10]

## RT6352-TFBGA_10
designator U?
footprint RT6352/BGA289/P0.65/12X12
part A pins: A1 RF0_PA2_V33P (in), A2 RF0_OUTP (out), A3 PLL_VC_CAP (out), A4 XTAL_XO (out), A6 ANT_TRN (out), B1 RF0_PA2_V33N (in), B2 RF0_OUTN (out), B3 PLL_VX_LDO, B4 XTAL_XI (out), B6 ANT_TRNB (out), C1 RF0_PA1_V33A (in), C2 RF1_VX_LDO, C3 RF0_VX_LDO, C4 XTAL_V12A (out), C6 PA_PE_G0 (out), D1 RF1_PA2_V33P (in), D2 RF1_PA2_V33N (in), D3 RF1_PA1_V33A (in), D4 BG_EXTR (out), D5 BG_V33A, D6 PA_PE_G1 (out), E1 RF1_OUTP (out), E2 RF1_OUTN (out), F3 WLED_N (out)
part B pins: F6 GND (power), F7 GND (power), F8 GND (power), F9 GND (power), F10 GND (power), F11 GND (power), F12 GND (power), G1 MD14 / MD15 (io), G2 MD9 / MD14 (io), G6 GND (power), G7 GND (power), G8 GND (power), G9 GND (power), G10 GND (power), G11 GND (power), G12 GND (power), H1 MD12 / MD13 (io), H2 MD11 / MD12 (io), H3 MRAS_N / MA5 (io), H4 MODT / MA4 (io), H5 DDR_IO_V18D/DDR_IO_V25D (in), J1 MD10 / MD11 (io), J2 MD13 / MD10 (io), J3 MCAS_N / MA7 (io), J4 MCS_N / MA6 (io), J5 DDR_IO_V18D/DDR_IO_V25D (in), K1 MD8 / MD9 (io), K2 MD15 / MD8 (io), K3 MA0 / MA8 (io), K4 MA2 / MA9 (io), K5 DDR_IOC_V12D (in), L1 MDQS1 (in), L2 MDQM1 (io), L3 MA6 / MA12 (io), L4 MA4 / MA11 (io), L5 DDR_IOC_V12D (in), M1 MCK_N (io), M2 MCK_P (io), M3 MA8 / MCKE (io), M5 MA11 / MODT (io), N1 MD5 / MD0 (io), N2 MD2 / MD1 (io), N3 MA9 / MA3 (io), N4 DDR_IO_VREF (in), N5 DDR_IO_V18D/DDR_IO_V25D (in), N6 DDR_IO_V18D/DDR_IO_V25D (in), P1 MD0 / MD2 (io), P2 MD7 / MD3 (io), P3 MA12 / MA2 (io), P4 MA7 / MA1 (io), P5 DDR_IO_VREF (in), R1 MD6 /MD4 (io), R2 MD1 / MD5 (io), R3 MA5 / MA0 (io), R4 MA3 / MA10 (io), T1 MD4 / MD6 (io), T2 MD3 / MD7 (io), T3 MA1 / MBA1 (io), T4 MBA0 / MCS_N (io), T5 MWE_N / MCAS_N (io), U1 MDQS0 (io), U2 MDQM0 (io), U3 MA10 / MBA0 (io), U4 MBA1 / MRAS_N (io), U5 MCKE / MWE_N (io)
part C pins: A7 SPI_CS0 (out), B7 SPI_CS1 (out), B17 PORST_N (in), C7 WDT_RST_N (out), C8 SPI_HOLD (out), D7 GPIO0, D8 SPI_WP (out), D9 SPI_MISO (in), D10 SPI_MOSI (out), D11 SPI_CLK (out), J6 GND (power), J7 GND (power), J8 GND (power), J9 GND (power), J10 GND (power), J11 GND (power), J12 GND (power), K6 GND (power), K7 GND (power), K8 GND (power), K9 GND (power), K10 GND (power), K11 GND (power), K12 GND (power), L6 GND (power), L7 GND (power), L8 GND (power), L9 GND (power), L10 GND (power), L11 GND (power), L12 GND (power), M6 GND (power), M7 GND (power), M8 GND (power), M9 GND (power), M10 GND (power), M11 GND (power), M12 GND (power), P6 TXD2, P7 RTS_N (out), P8 ND_D3/SD_D3 (out), P9 ND_D2/SD_D2 (out), P10 ND_D1/SD_D1 (out), P11 DSR_N (io), P12 RXD (io), R6 RXD2 (in), R7 ND_D5/bt_aux (out), R8 ND_CS_N (out), R9 ND_WP/SD_WP (out), R10 ND_D0/SD_D0 (out), R11 DCD_N (io), R12 RIN (io), T6 I2C_SD (out), T7 ND_D6/bt_wact (out), T8 ND_CLE/SD_card_detect, T9 ND_WE_N (out), T10 ND_ALE/SD_CMD (out), T11 TXD (out), T12 CTS_N (io), U6 I2C_SCLK (io), U7 ND_D7/bt_ant (out), U8 ND_D4/bt_stat (out), U9 ND_RE_N (out), U10 ND_RB_N/SD_CLK (out), U11 DTR_N (out)
part D pins: A8 APCK_RFCKOP (out), A9 PCIE_RXN (out), A10 PCIE_TXP, A11 PCIE_RFCKP (out), B8 APCK_RFCKON (out), B9 PCIE_RXP (out), B10 PCIE_TXN, B11 PCIE_RFCKN (out), C5 GND, C9 PCIE_REXT, C10 PERST_N, C16 UPHY0_PADP (io), C17 UPHY0_PADM (io), D16 UPHY1_PADM (io), D17 UPHY1_PADP (io), E3 GND, E4 GND, E8 PCIE_V12A (out), E12 UPHY0_V12D (in), E13 UPHY0_V12D (in), E14 UPHY1_V33A (in), E15 UPHY1_V33A (in), E16 UPHY0_VRES (io), E17 UPHY1_VRES (io), H6 GND (power), H7 GND (power), H8 GND (power), H9 GND (power), H10 GND (power), H11 GND (power), H12 GND (power), K3 GND, R17 GND, U5 GND, U12 GND
part E pins: F1 EPHY_LED3_N_JTCLK (out), F2 EPHY_LED2_N_JTMS (out), F4 EPHY_LED1_N_JTDI (out), F14 GE2_RXD0 (in), F15 GE2_RXD1 (in), F16 GE1_RXD2 (in), F17 GE1_RXD3 (in), G3 EPHY_LED0_N_JTDO (out), G4 EPHY_LED4_N_JTRST_N (out), G14 GE2_RXD2 (in), G15 GE1_RXDV (in), G16 GE1_RXD0 (in), G17 GE1_RXD1 (in), H13 GE_RGMII_IO_V33D (in), H14 GE2_RXD3 (in), H15 GE1_RXCLK (io), H16 GE1_RXCLK (io), H17 GE1_RXDV (in), J13 GE_RGMII_IO_V33D (in), J14 GE2_TXD1 (out), J15 GE2_TXD0 (out), J16 GE1_TXD0 (out), J17 GE1_TXD1 (out), K14 GE2_TXD3 (out), K15 GE2_TXD2 (out), K16 GE1_TXD2 (out), K17 GE1_TXD3 (out), L14 GE2_TXEN (out), L15 GE2_TXCLK (io), L16 GE1_TXCLK (io), L17 GE1_TXEN (out), M13 EPHY_V12A (in), M14 MDIO (io), M15 MDC (out), M17 EPHY_RES_VBG (io), N12 EPHY_V12A (in), N13 EPHY_V33A (in), N14 MDI_TN_P0 (out), N15 MDI_TP_P0 (out), N16 MDI_RN_P0 (in), N17 MDI_RP_P0 (in), P13 EPHY_V33A (in), P14 MDI_RN_P1 (in), P15 MDI_TP_P2 (out), P16 MDI_TN_P4 (out), P17 MDI_TP_P4 (out), R13 EPHY_V33A (in), R14 MDI_RP_P1 (in), R15 MDI_TN_P2 (out), R16 MDI_RN_P4 (in), R17 MDI_RP_P4 (in), T14 MDI_TN_P1 (out), T15 MDI_RP_P2 (in), T16 MDI_TN_P3 (out), T17 MDI_RN_P3 (in), U14 MDI_TP_P1 (out), U15 MDI_RN_P2 (in), U16 MDI_TP_P3 (out), U17 MDI_RP_P3 (in)
part F pins: A5 BBPLL_V12A (in), A14 COMP (in), A15 UGATE (in), A16 DCDC_V33D (in), A17 VFB_DIG (in), B5 BBPLL_V12D (in), B14 FB (in), B15 LGATE (in), B16 EXT_LDO_DIG (out), C11 APCK_VCCA (in), C13 EXT_LDO_DDR (out), C15 DCDC_V33A (in), D12 PCIE_V33A (in), D13 VFB_DDR (in), E6 SOC_IO_V33D_0 (in), E7 SOC_CO_V12D_0 (in), F5 SOC_IO_V33D_1 (in), G5 SOC_CO_V12D_1 (in), N7 SOC_CO_V12D_2 (in), N8 SOC_CO_V12D_2 (in), N10 SOC_IO_V33D_2 (in), N11 SOC_IO_V33D_2 (in)

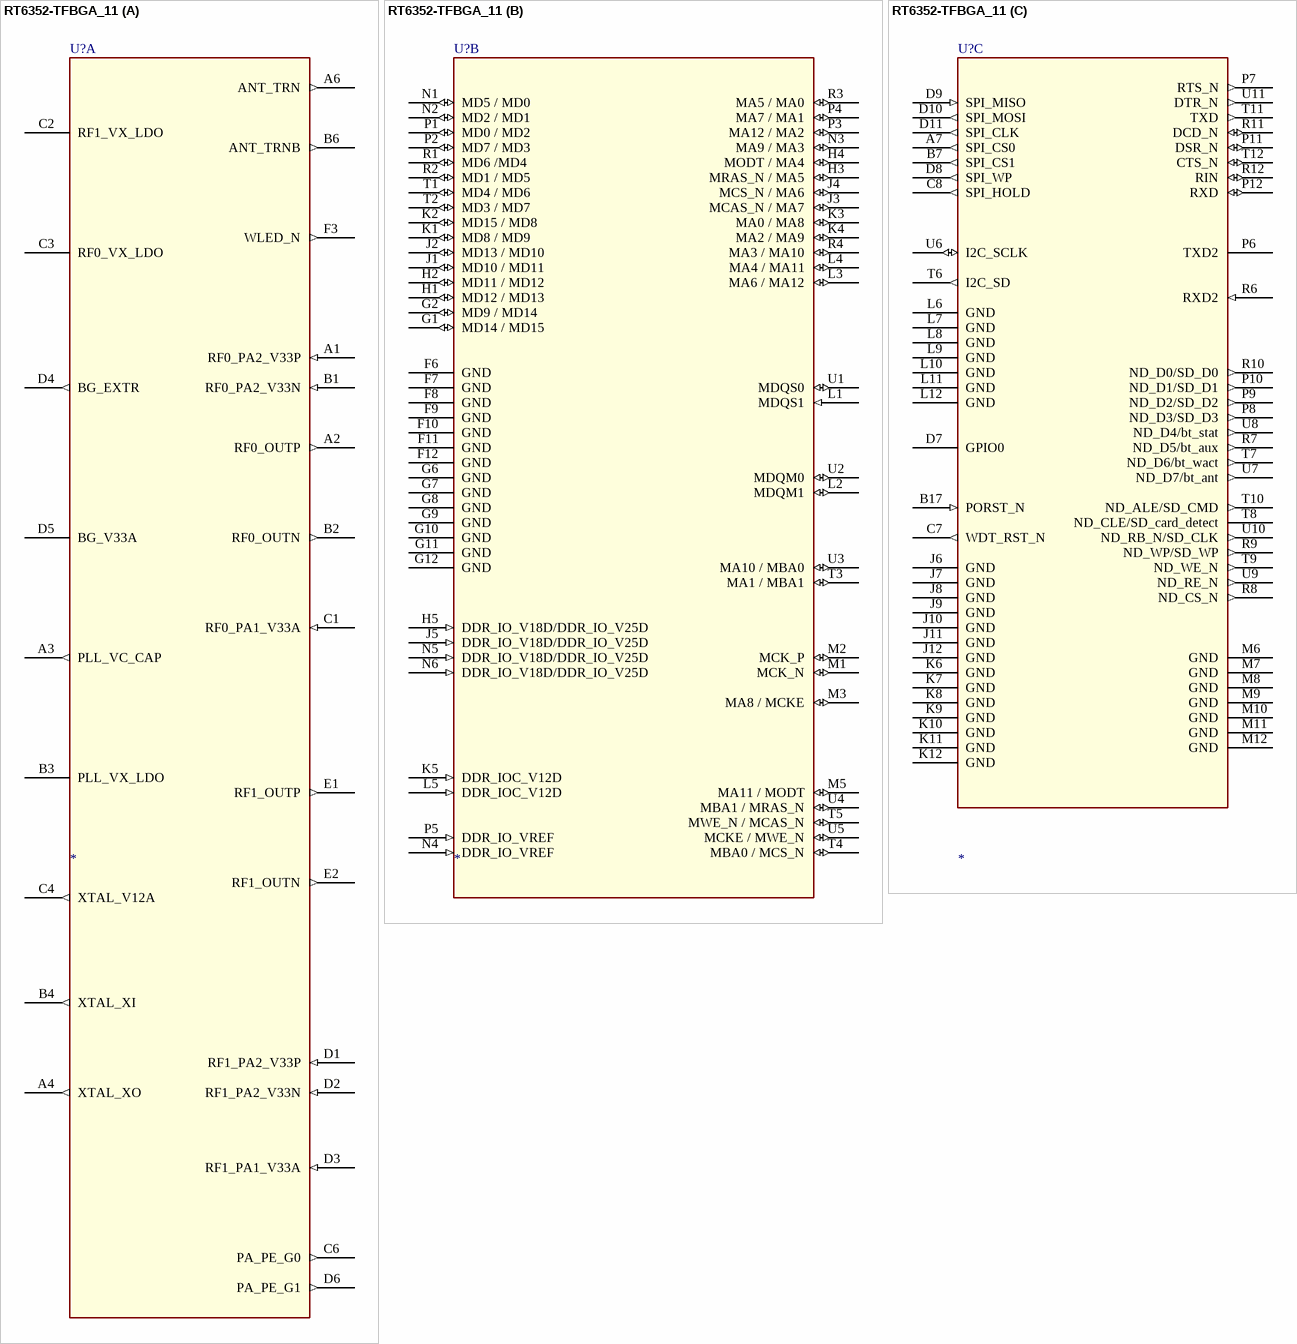
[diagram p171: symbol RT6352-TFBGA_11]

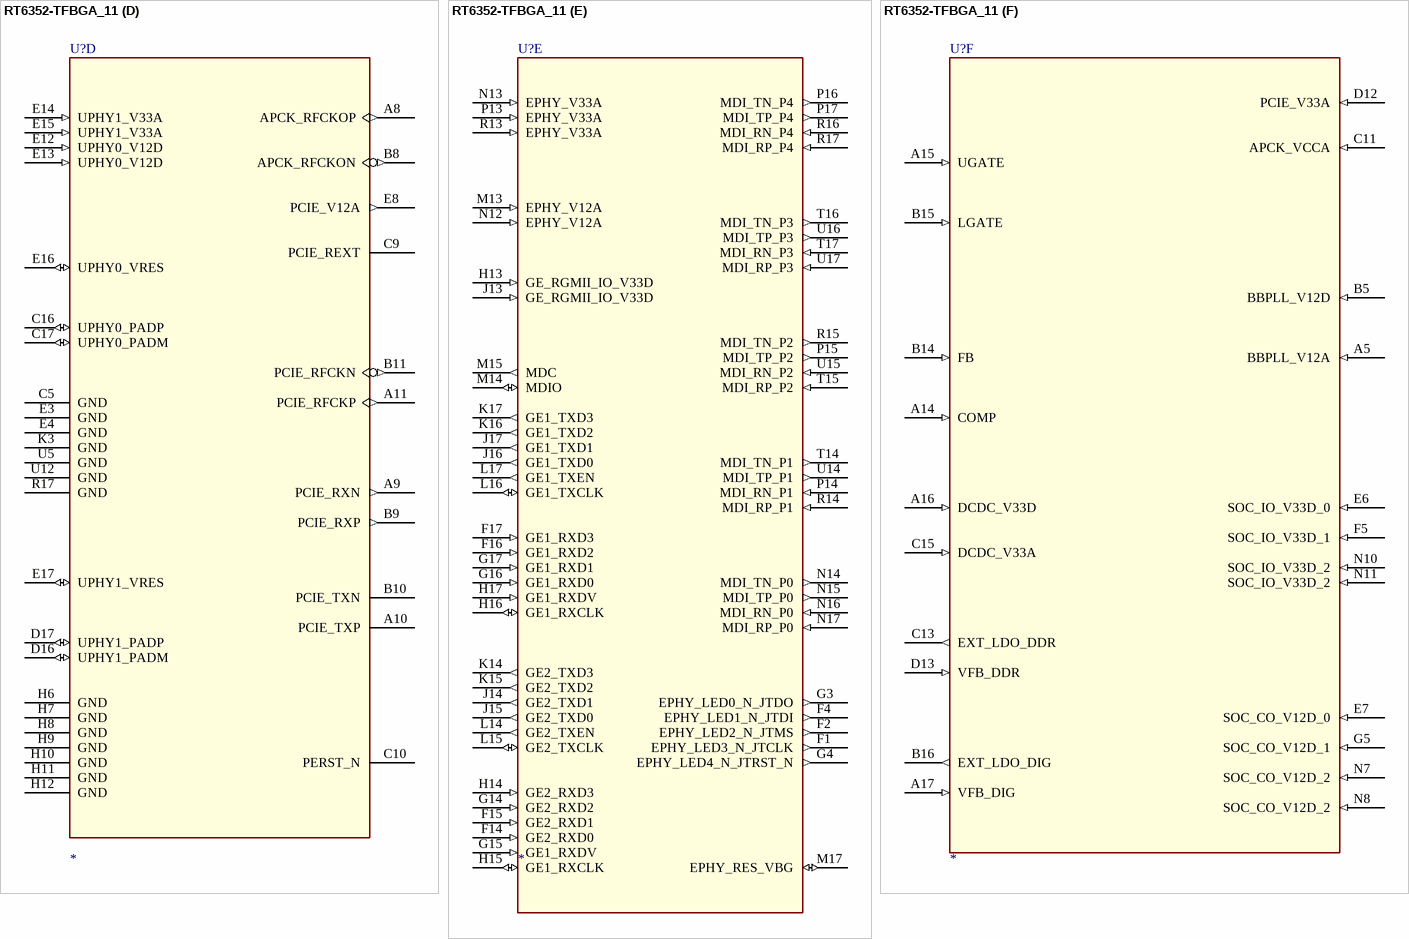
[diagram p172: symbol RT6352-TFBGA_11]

## RT6352-TFBGA_11
designator U?
footprint RT6352/BGA289/P0.65/12X12
part A pins: A1 RF0_PA2_V33P (in), A2 RF0_OUTP (out), A3 PLL_VC_CAP (out), A4 XTAL_XO (out), A6 ANT_TRN (out), B1 RF0_PA2_V33N (in), B2 RF0_OUTN (out), B3 PLL_VX_LDO, B4 XTAL_XI (out), B6 ANT_TRNB (out), C1 RF0_PA1_V33A (in), C2 RF1_VX_LDO, C3 RF0_VX_LDO, C4 XTAL_V12A (out), C6 PA_PE_G0 (out), D1 RF1_PA2_V33P (in), D2 RF1_PA2_V33N (in), D3 RF1_PA1_V33A (in), D4 BG_EXTR (out), D5 BG_V33A, D6 PA_PE_G1 (out), E1 RF1_OUTP (out), E2 RF1_OUTN (out), F3 WLED_N (out)
part B pins: F6 GND (power), F7 GND (power), F8 GND (power), F9 GND (power), F10 GND (power), F11 GND (power), F12 GND (power), G1 MD14 / MD15 (io), G2 MD9 / MD14 (io), G6 GND (power), G7 GND (power), G8 GND (power), G9 GND (power), G10 GND (power), G11 GND (power), G12 GND (power), H1 MD12 / MD13 (io), H2 MD11 / MD12 (io), H3 MRAS_N / MA5 (io), H4 MODT / MA4 (io), H5 DDR_IO_V18D/DDR_IO_V25D (in), J1 MD10 / MD11 (io), J2 MD13 / MD10 (io), J3 MCAS_N / MA7 (io), J4 MCS_N / MA6 (io), J5 DDR_IO_V18D/DDR_IO_V25D (in), K1 MD8 / MD9 (io), K2 MD15 / MD8 (io), K3 MA0 / MA8 (io), K4 MA2 / MA9 (io), K5 DDR_IOC_V12D (in), L1 MDQS1 (in), L2 MDQM1 (io), L3 MA6 / MA12 (io), L4 MA4 / MA11 (io), L5 DDR_IOC_V12D (in), M1 MCK_N (io), M2 MCK_P (io), M3 MA8 / MCKE (io), M5 MA11 / MODT (io), N1 MD5 / MD0 (io), N2 MD2 / MD1 (io), N3 MA9 / MA3 (io), N4 DDR_IO_VREF (in), N5 DDR_IO_V18D/DDR_IO_V25D (in), N6 DDR_IO_V18D/DDR_IO_V25D (in), P1 MD0 / MD2 (io), P2 MD7 / MD3 (io), P3 MA12 / MA2 (io), P4 MA7 / MA1 (io), P5 DDR_IO_VREF (in), R1 MD6 /MD4 (io), R2 MD1 / MD5 (io), R3 MA5 / MA0 (io), R4 MA3 / MA10 (io), T1 MD4 / MD6 (io), T2 MD3 / MD7 (io), T3 MA1 / MBA1 (io), T4 MBA0 / MCS_N (io), T5 MWE_N / MCAS_N (io), U1 MDQS0 (io), U2 MDQM0 (io), U3 MA10 / MBA0 (io), U4 MBA1 / MRAS_N (io), U5 MCKE / MWE_N (io)
part C pins: A7 SPI_CS0 (out), B7 SPI_CS1 (out), B17 PORST_N (in), C7 WDT_RST_N (out), C8 SPI_HOLD (out), D7 GPIO0, D8 SPI_WP (out), D9 SPI_MISO (in), D10 SPI_MOSI (out), D11 SPI_CLK (out), J6 GND (power), J7 GND (power), J8 GND (power), J9 GND (power), J10 GND (power), J11 GND (power), J12 GND (power), K6 GND (power), K7 GND (power), K8 GND (power), K9 GND (power), K10 GND (power), K11 GND (power), K12 GND (power), L6 GND (power), L7 GND (power), L8 GND (power), L9 GND (power), L10 GND (power), L11 GND (power), L12 GND (power), M6 GND (power), M7 GND (power), M8 GND (power), M9 GND (power), M10 GND (power), M11 GND (power), M12 GND (power), P6 TXD2, P7 RTS_N (out), P8 ND_D3/SD_D3 (out), P9 ND_D2/SD_D2 (out), P10 ND_D1/SD_D1 (out), P11 DSR_N (io), P12 RXD (io), R6 RXD2 (in), R7 ND_D5/bt_aux (out), R8 ND_CS_N (out), R9 ND_WP/SD_WP (out), R10 ND_D0/SD_D0 (out), R11 DCD_N (io), R12 RIN (io), T6 I2C_SD (out), T7 ND_D6/bt_wact (out), T8 ND_CLE/SD_card_detect, T9 ND_WE_N (out), T10 ND_ALE/SD_CMD (out), T11 TXD (out), T12 CTS_N (io), U6 I2C_SCLK (io), U7 ND_D7/bt_ant (out), U8 ND_D4/bt_stat (out), U9 ND_RE_N (out), U10 ND_RB_N/SD_CLK (out), U11 DTR_N (out)
part D pins: A8 APCK_RFCKOP (out), A9 PCIE_RXN (out), A10 PCIE_TXP, A11 PCIE_RFCKP (out), B8 APCK_RFCKON (out), B9 PCIE_RXP (out), B10 PCIE_TXN, B11 PCIE_RFCKN (out), C5 GND, C9 PCIE_REXT, C10 PERST_N, C16 UPHY0_PADP (io), C17 UPHY0_PADM (io), D16 UPHY1_PADM (io), D17 UPHY1_PADP (io), E3 GND, E4 GND, E8 PCIE_V12A (out), E12 UPHY0_V12D (in), E13 UPHY0_V12D (in), E14 UPHY1_V33A (in), E15 UPHY1_V33A (in), E16 UPHY0_VRES (io), E17 UPHY1_VRES (io), H6 GND (power), H7 GND (power), H8 GND (power), H9 GND (power), H10 GND (power), H11 GND (power), H12 GND (power), K3 GND, R17 GND, U5 GND, U12 GND
part E pins: F1 EPHY_LED3_N_JTCLK (out), F2 EPHY_LED2_N_JTMS (out), F4 EPHY_LED1_N_JTDI (out), F14 GE2_RXD0 (in), F15 GE2_RXD1 (in), F16 GE1_RXD2 (in), F17 GE1_RXD3 (in), G3 EPHY_LED0_N_JTDO (out), G4 EPHY_LED4_N_JTRST_N (out), G14 GE2_RXD2 (in), G15 GE1_RXDV (in), G16 GE1_RXD0 (in), G17 GE1_RXD1 (in), H13 GE_RGMII_IO_V33D (in), H14 GE2_RXD3 (in), H15 GE1_RXCLK (io), H16 GE1_RXCLK (io), H17 GE1_RXDV (in), J13 GE_RGMII_IO_V33D (in), J14 GE2_TXD1 (out), J15 GE2_TXD0 (out), J16 GE1_TXD0 (out), J17 GE1_TXD1 (out), K14 GE2_TXD3 (out), K15 GE2_TXD2 (out), K16 GE1_TXD2 (out), K17 GE1_TXD3 (out), L14 GE2_TXEN (out), L15 GE2_TXCLK (io), L16 GE1_TXCLK (io), L17 GE1_TXEN (out), M13 EPHY_V12A (in), M14 MDIO (io), M15 MDC (out), M17 EPHY_RES_VBG (io), N12 EPHY_V12A (in), N13 EPHY_V33A (in), N14 MDI_TN_P0 (out), N15 MDI_TP_P0 (out), N16 MDI_RN_P0 (in), N17 MDI_RP_P0 (in), P13 EPHY_V33A (in), P14 MDI_RN_P1 (in), P15 MDI_TP_P2 (out), P16 MDI_TN_P4 (out), P17 MDI_TP_P4 (out), R13 EPHY_V33A (in), R14 MDI_RP_P1 (in), R15 MDI_TN_P2 (out), R16 MDI_RN_P4 (in), R17 MDI_RP_P4 (in), T14 MDI_TN_P1 (out), T15 MDI_RP_P2 (in), T16 MDI_TN_P3 (out), T17 MDI_RN_P3 (in), U14 MDI_TP_P1 (out), U15 MDI_RN_P2 (in), U16 MDI_TP_P3 (out), U17 MDI_RP_P3 (in)
part F pins: A5 BBPLL_V12A (in), A14 COMP (in), A15 UGATE (in), A16 DCDC_V33D (in), A17 VFB_DIG (in), B5 BBPLL_V12D (in), B14 FB (in), B15 LGATE (in), B16 EXT_LDO_DIG (out), C11 APCK_VCCA (in), C13 EXT_LDO_DDR (out), C15 DCDC_V33A (in), D12 PCIE_V33A (in), D13 VFB_DDR (in), E6 SOC_IO_V33D_0 (in), E7 SOC_CO_V12D_0 (in), F5 SOC_IO_V33D_1 (in), G5 SOC_CO_V12D_1 (in), N7 SOC_CO_V12D_2 (in), N8 SOC_CO_V12D_2 (in), N10 SOC_IO_V33D_2 (in), N11 SOC_IO_V33D_2 (in)

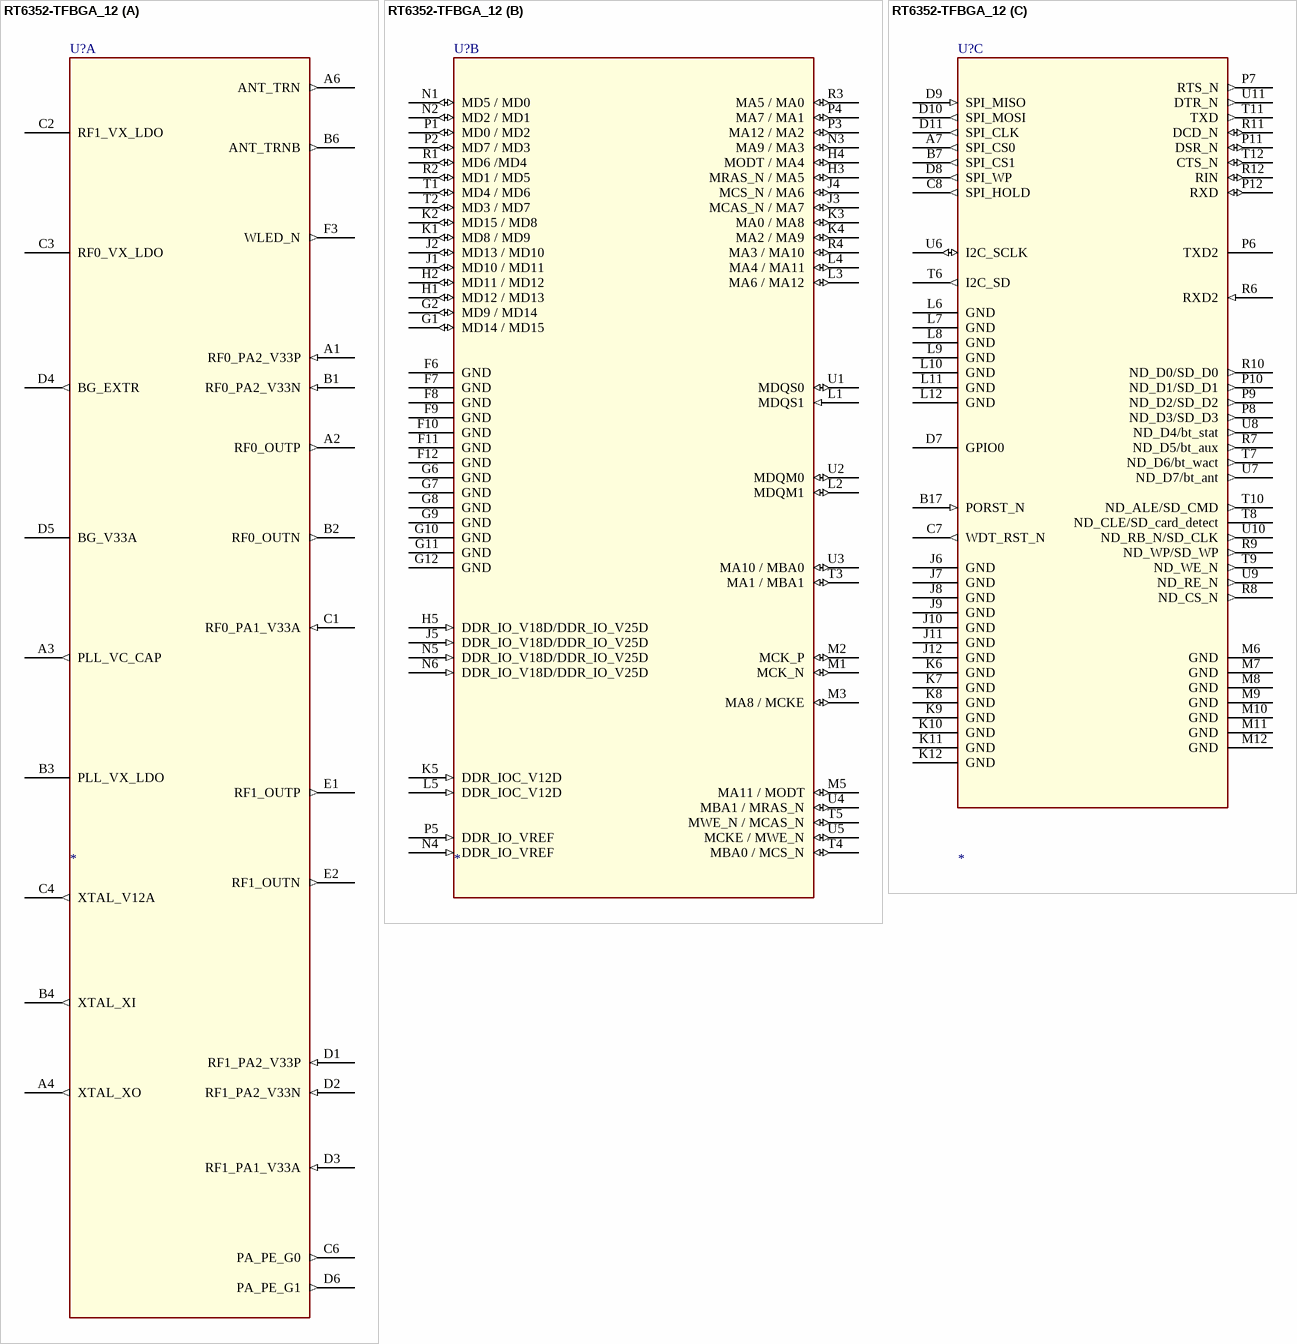
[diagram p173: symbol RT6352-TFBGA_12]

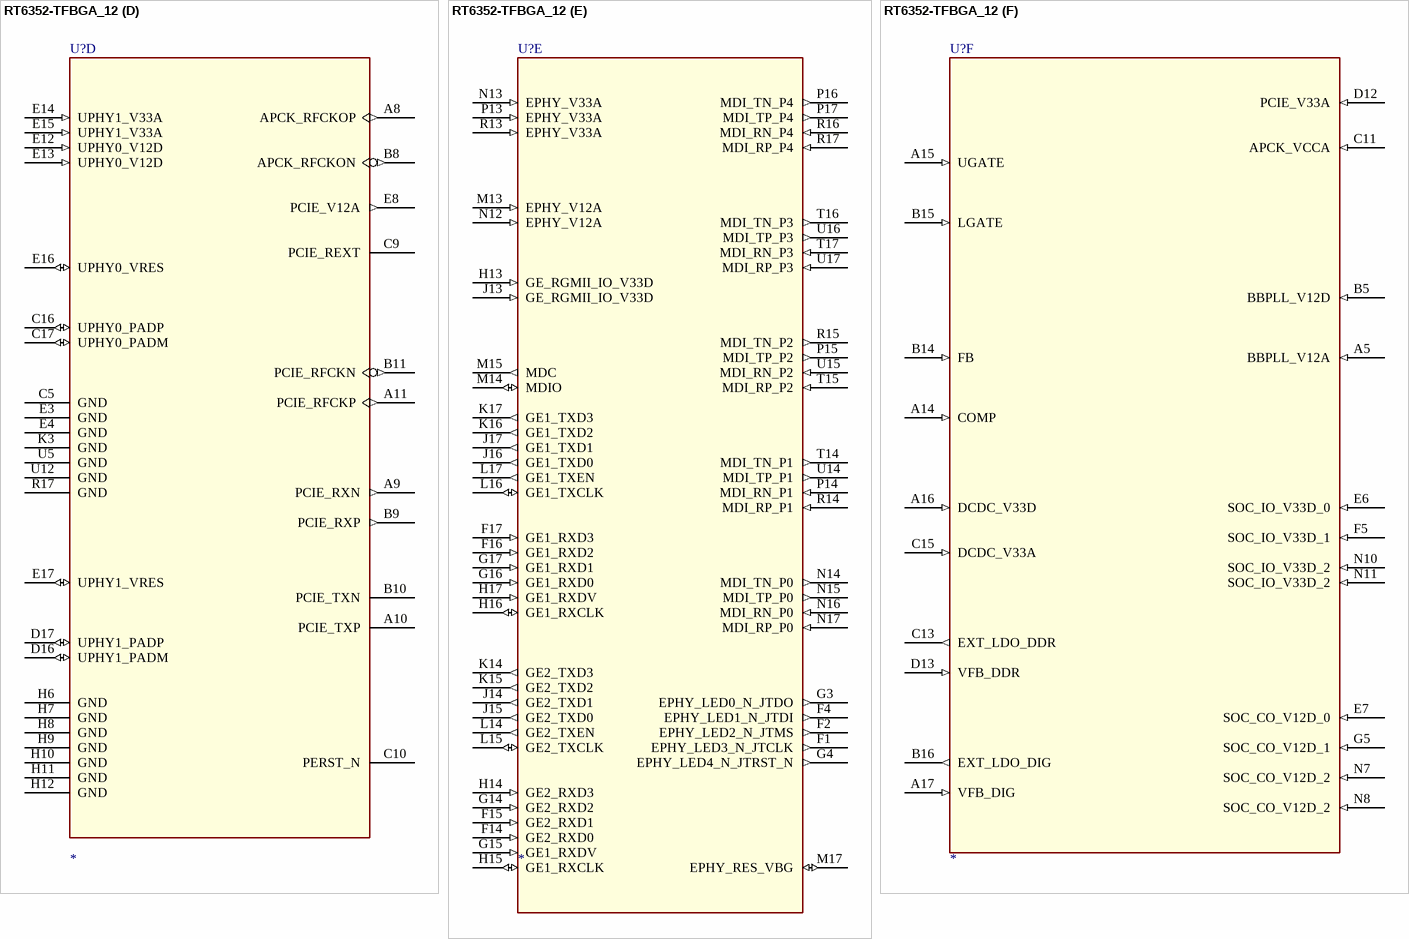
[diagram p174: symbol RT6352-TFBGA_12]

## RT6352-TFBGA_12
designator U?
footprint RT6352/BGA289/P0.65/12X12
part A pins: A1 RF0_PA2_V33P (in), A2 RF0_OUTP (out), A3 PLL_VC_CAP (out), A4 XTAL_XO (out), A6 ANT_TRN (out), B1 RF0_PA2_V33N (in), B2 RF0_OUTN (out), B3 PLL_VX_LDO, B4 XTAL_XI (out), B6 ANT_TRNB (out), C1 RF0_PA1_V33A (in), C2 RF1_VX_LDO, C3 RF0_VX_LDO, C4 XTAL_V12A (out), C6 PA_PE_G0 (out), D1 RF1_PA2_V33P (in), D2 RF1_PA2_V33N (in), D3 RF1_PA1_V33A (in), D4 BG_EXTR (out), D5 BG_V33A, D6 PA_PE_G1 (out), E1 RF1_OUTP (out), E2 RF1_OUTN (out), F3 WLED_N (out)
part B pins: F6 GND (power), F7 GND (power), F8 GND (power), F9 GND (power), F10 GND (power), F11 GND (power), F12 GND (power), G1 MD14 / MD15 (io), G2 MD9 / MD14 (io), G6 GND (power), G7 GND (power), G8 GND (power), G9 GND (power), G10 GND (power), G11 GND (power), G12 GND (power), H1 MD12 / MD13 (io), H2 MD11 / MD12 (io), H3 MRAS_N / MA5 (io), H4 MODT / MA4 (io), H5 DDR_IO_V18D/DDR_IO_V25D (in), J1 MD10 / MD11 (io), J2 MD13 / MD10 (io), J3 MCAS_N / MA7 (io), J4 MCS_N / MA6 (io), J5 DDR_IO_V18D/DDR_IO_V25D (in), K1 MD8 / MD9 (io), K2 MD15 / MD8 (io), K3 MA0 / MA8 (io), K4 MA2 / MA9 (io), K5 DDR_IOC_V12D (in), L1 MDQS1 (in), L2 MDQM1 (io), L3 MA6 / MA12 (io), L4 MA4 / MA11 (io), L5 DDR_IOC_V12D (in), M1 MCK_N (io), M2 MCK_P (io), M3 MA8 / MCKE (io), M5 MA11 / MODT (io), N1 MD5 / MD0 (io), N2 MD2 / MD1 (io), N3 MA9 / MA3 (io), N4 DDR_IO_VREF (in), N5 DDR_IO_V18D/DDR_IO_V25D (in), N6 DDR_IO_V18D/DDR_IO_V25D (in), P1 MD0 / MD2 (io), P2 MD7 / MD3 (io), P3 MA12 / MA2 (io), P4 MA7 / MA1 (io), P5 DDR_IO_VREF (in), R1 MD6 /MD4 (io), R2 MD1 / MD5 (io), R3 MA5 / MA0 (io), R4 MA3 / MA10 (io), T1 MD4 / MD6 (io), T2 MD3 / MD7 (io), T3 MA1 / MBA1 (io), T4 MBA0 / MCS_N (io), T5 MWE_N / MCAS_N (io), U1 MDQS0 (io), U2 MDQM0 (io), U3 MA10 / MBA0 (io), U4 MBA1 / MRAS_N (io), U5 MCKE / MWE_N (io)
part C pins: A7 SPI_CS0 (out), B7 SPI_CS1 (out), B17 PORST_N (in), C7 WDT_RST_N (out), C8 SPI_HOLD (out), D7 GPIO0, D8 SPI_WP (out), D9 SPI_MISO (in), D10 SPI_MOSI (out), D11 SPI_CLK (out), J6 GND (power), J7 GND (power), J8 GND (power), J9 GND (power), J10 GND (power), J11 GND (power), J12 GND (power), K6 GND (power), K7 GND (power), K8 GND (power), K9 GND (power), K10 GND (power), K11 GND (power), K12 GND (power), L6 GND (power), L7 GND (power), L8 GND (power), L9 GND (power), L10 GND (power), L11 GND (power), L12 GND (power), M6 GND (power), M7 GND (power), M8 GND (power), M9 GND (power), M10 GND (power), M11 GND (power), M12 GND (power), P6 TXD2, P7 RTS_N (out), P8 ND_D3/SD_D3 (out), P9 ND_D2/SD_D2 (out), P10 ND_D1/SD_D1 (out), P11 DSR_N (io), P12 RXD (io), R6 RXD2 (in), R7 ND_D5/bt_aux (out), R8 ND_CS_N (out), R9 ND_WP/SD_WP (out), R10 ND_D0/SD_D0 (out), R11 DCD_N (io), R12 RIN (io), T6 I2C_SD (out), T7 ND_D6/bt_wact (out), T8 ND_CLE/SD_card_detect, T9 ND_WE_N (out), T10 ND_ALE/SD_CMD (out), T11 TXD (out), T12 CTS_N (io), U6 I2C_SCLK (io), U7 ND_D7/bt_ant (out), U8 ND_D4/bt_stat (out), U9 ND_RE_N (out), U10 ND_RB_N/SD_CLK (out), U11 DTR_N (out)
part D pins: A8 APCK_RFCKOP (out), A9 PCIE_RXN (out), A10 PCIE_TXP, A11 PCIE_RFCKP (out), B8 APCK_RFCKON (out), B9 PCIE_RXP (out), B10 PCIE_TXN, B11 PCIE_RFCKN (out), C5 GND, C9 PCIE_REXT, C10 PERST_N, C16 UPHY0_PADP (io), C17 UPHY0_PADM (io), D16 UPHY1_PADM (io), D17 UPHY1_PADP (io), E3 GND, E4 GND, E8 PCIE_V12A (out), E12 UPHY0_V12D (in), E13 UPHY0_V12D (in), E14 UPHY1_V33A (in), E15 UPHY1_V33A (in), E16 UPHY0_VRES (io), E17 UPHY1_VRES (io), H6 GND (power), H7 GND (power), H8 GND (power), H9 GND (power), H10 GND (power), H11 GND (power), H12 GND (power), K3 GND, R17 GND, U5 GND, U12 GND
part E pins: F1 EPHY_LED3_N_JTCLK (out), F2 EPHY_LED2_N_JTMS (out), F4 EPHY_LED1_N_JTDI (out), F14 GE2_RXD0 (in), F15 GE2_RXD1 (in), F16 GE1_RXD2 (in), F17 GE1_RXD3 (in), G3 EPHY_LED0_N_JTDO (out), G4 EPHY_LED4_N_JTRST_N (out), G14 GE2_RXD2 (in), G15 GE1_RXDV (in), G16 GE1_RXD0 (in), G17 GE1_RXD1 (in), H13 GE_RGMII_IO_V33D (in), H14 GE2_RXD3 (in), H15 GE1_RXCLK (io), H16 GE1_RXCLK (io), H17 GE1_RXDV (in), J13 GE_RGMII_IO_V33D (in), J14 GE2_TXD1 (out), J15 GE2_TXD0 (out), J16 GE1_TXD0 (out), J17 GE1_TXD1 (out), K14 GE2_TXD3 (out), K15 GE2_TXD2 (out), K16 GE1_TXD2 (out), K17 GE1_TXD3 (out), L14 GE2_TXEN (out), L15 GE2_TXCLK (io), L16 GE1_TXCLK (io), L17 GE1_TXEN (out), M13 EPHY_V12A (in), M14 MDIO (io), M15 MDC (out), M17 EPHY_RES_VBG (io), N12 EPHY_V12A (in), N13 EPHY_V33A (in), N14 MDI_TN_P0 (out), N15 MDI_TP_P0 (out), N16 MDI_RN_P0 (in), N17 MDI_RP_P0 (in), P13 EPHY_V33A (in), P14 MDI_RN_P1 (in), P15 MDI_TP_P2 (out), P16 MDI_TN_P4 (out), P17 MDI_TP_P4 (out), R13 EPHY_V33A (in), R14 MDI_RP_P1 (in), R15 MDI_TN_P2 (out), R16 MDI_RN_P4 (in), R17 MDI_RP_P4 (in), T14 MDI_TN_P1 (out), T15 MDI_RP_P2 (in), T16 MDI_TN_P3 (out), T17 MDI_RN_P3 (in), U14 MDI_TP_P1 (out), U15 MDI_RN_P2 (in), U16 MDI_TP_P3 (out), U17 MDI_RP_P3 (in)
part F pins: A5 BBPLL_V12A (in), A14 COMP (in), A15 UGATE (in), A16 DCDC_V33D (in), A17 VFB_DIG (in), B5 BBPLL_V12D (in), B14 FB (in), B15 LGATE (in), B16 EXT_LDO_DIG (out), C11 APCK_VCCA (in), C13 EXT_LDO_DDR (out), C15 DCDC_V33A (in), D12 PCIE_V33A (in), D13 VFB_DDR (in), E6 SOC_IO_V33D_0 (in), E7 SOC_CO_V12D_0 (in), F5 SOC_IO_V33D_1 (in), G5 SOC_CO_V12D_1 (in), N7 SOC_CO_V12D_2 (in), N8 SOC_CO_V12D_2 (in), N10 SOC_IO_V33D_2 (in), N11 SOC_IO_V33D_2 (in)

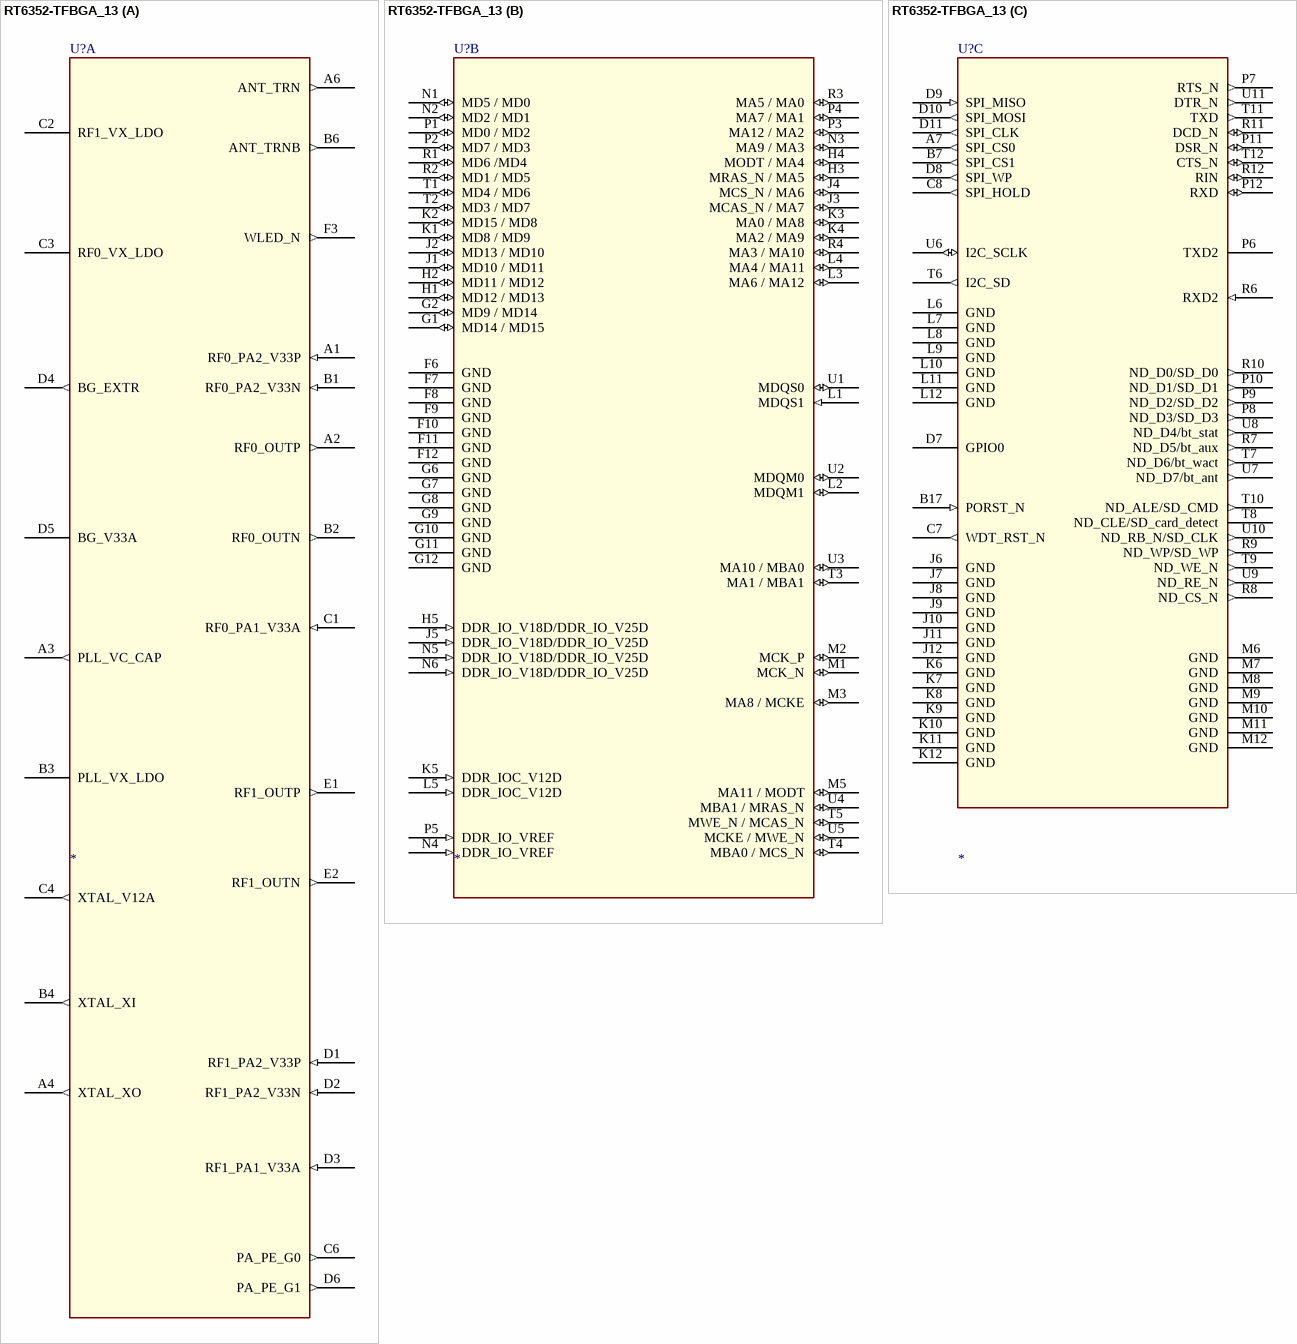
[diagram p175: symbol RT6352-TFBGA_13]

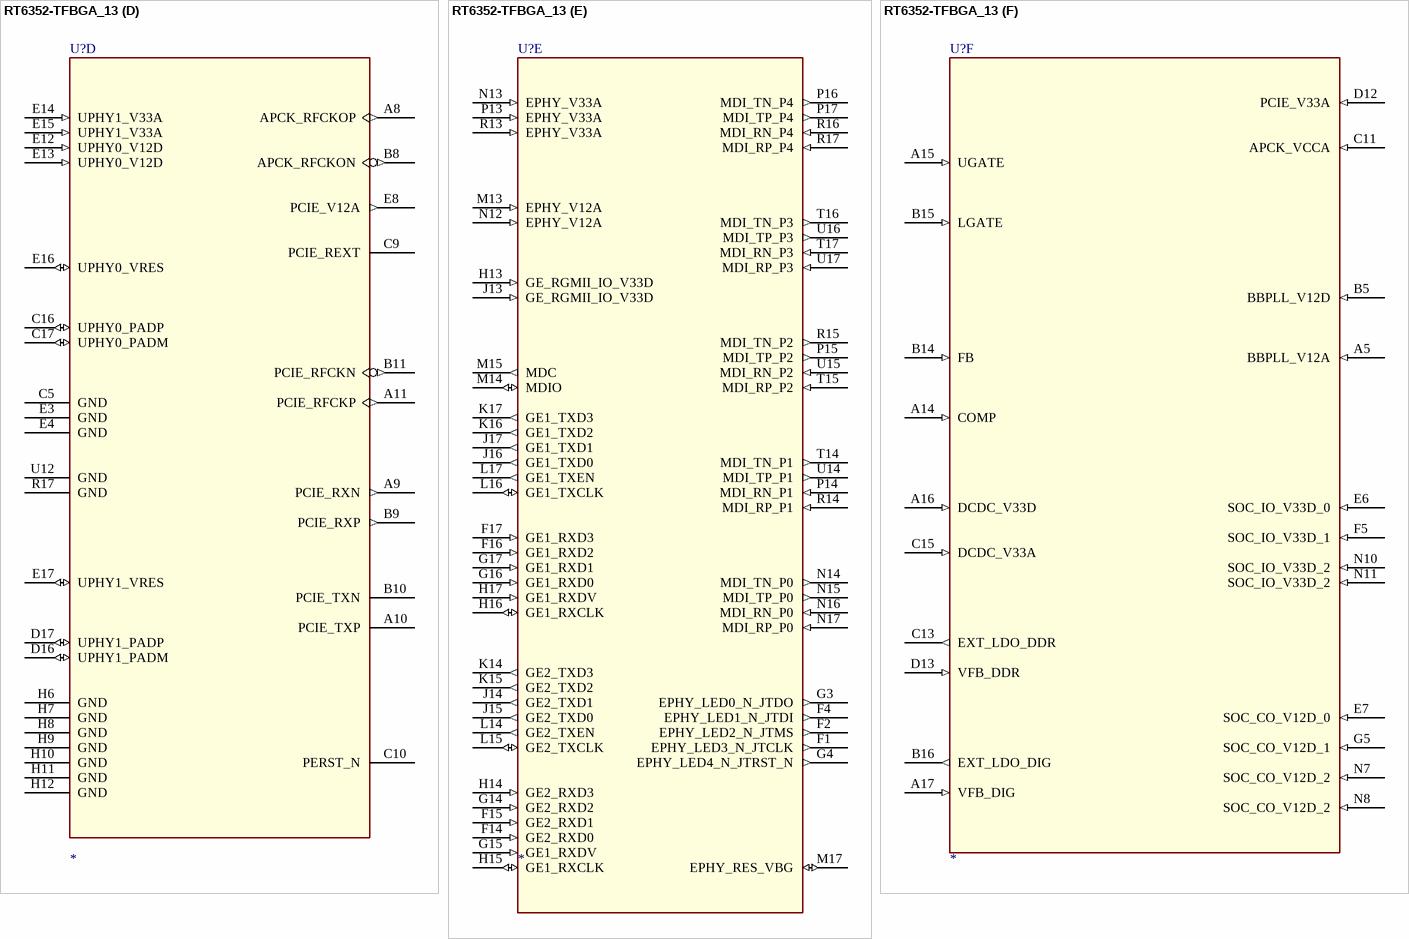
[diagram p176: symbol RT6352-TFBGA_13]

## RT6352-TFBGA_13
designator U?
footprint RT6352/BGA289/P0.65/12X12
part A pins: A1 RF0_PA2_V33P (in), A2 RF0_OUTP (out), A3 PLL_VC_CAP (out), A4 XTAL_XO (out), A6 ANT_TRN (out), B1 RF0_PA2_V33N (in), B2 RF0_OUTN (out), B3 PLL_VX_LDO, B4 XTAL_XI (out), B6 ANT_TRNB (out), C1 RF0_PA1_V33A (in), C2 RF1_VX_LDO, C3 RF0_VX_LDO, C4 XTAL_V12A (out), C6 PA_PE_G0 (out), D1 RF1_PA2_V33P (in), D2 RF1_PA2_V33N (in), D3 RF1_PA1_V33A (in), D4 BG_EXTR (out), D5 BG_V33A, D6 PA_PE_G1 (out), E1 RF1_OUTP (out), E2 RF1_OUTN (out), F3 WLED_N (out)
part B pins: F6 GND (power), F7 GND (power), F8 GND (power), F9 GND (power), F10 GND (power), F11 GND (power), F12 GND (power), G1 MD14 / MD15 (io), G2 MD9 / MD14 (io), G6 GND (power), G7 GND (power), G8 GND (power), G9 GND (power), G10 GND (power), G11 GND (power), G12 GND (power), H1 MD12 / MD13 (io), H2 MD11 / MD12 (io), H3 MRAS_N / MA5 (io), H4 MODT / MA4 (io), H5 DDR_IO_V18D/DDR_IO_V25D (in), J1 MD10 / MD11 (io), J2 MD13 / MD10 (io), J3 MCAS_N / MA7 (io), J4 MCS_N / MA6 (io), J5 DDR_IO_V18D/DDR_IO_V25D (in), K1 MD8 / MD9 (io), K2 MD15 / MD8 (io), K3 MA0 / MA8 (io), K4 MA2 / MA9 (io), K5 DDR_IOC_V12D (in), L1 MDQS1 (in), L2 MDQM1 (io), L3 MA6 / MA12 (io), L4 MA4 / MA11 (io), L5 DDR_IOC_V12D (in), M1 MCK_N (io), M2 MCK_P (io), M3 MA8 / MCKE (io), M5 MA11 / MODT (io), N1 MD5 / MD0 (io), N2 MD2 / MD1 (io), N3 MA9 / MA3 (io), N4 DDR_IO_VREF (in), N5 DDR_IO_V18D/DDR_IO_V25D (in), N6 DDR_IO_V18D/DDR_IO_V25D (in), P1 MD0 / MD2 (io), P2 MD7 / MD3 (io), P3 MA12 / MA2 (io), P4 MA7 / MA1 (io), P5 DDR_IO_VREF (in), R1 MD6 /MD4 (io), R2 MD1 / MD5 (io), R3 MA5 / MA0 (io), R4 MA3 / MA10 (io), T1 MD4 / MD6 (io), T2 MD3 / MD7 (io), T3 MA1 / MBA1 (io), T4 MBA0 / MCS_N (io), T5 MWE_N / MCAS_N (io), U1 MDQS0 (io), U2 MDQM0 (io), U3 MA10 / MBA0 (io), U4 MBA1 / MRAS_N (io), U5 MCKE / MWE_N (io)
part C pins: A7 SPI_CS0 (out), B7 SPI_CS1 (out), B17 PORST_N (in), C7 WDT_RST_N (out), C8 SPI_HOLD (out), D7 GPIO0, D8 SPI_WP (out), D9 SPI_MISO (in), D10 SPI_MOSI (out), D11 SPI_CLK (out), J6 GND (power), J7 GND (power), J8 GND (power), J9 GND (power), J10 GND (power), J11 GND (power), J12 GND (power), K6 GND (power), K7 GND (power), K8 GND (power), K9 GND (power), K10 GND (power), K11 GND (power), K12 GND (power), L6 GND (power), L7 GND (power), L8 GND (power), L9 GND (power), L10 GND (power), L11 GND (power), L12 GND (power), M6 GND (power), M7 GND (power), M8 GND (power), M9 GND (power), M10 GND (power), M11 GND (power), M12 GND (power), P6 TXD2, P7 RTS_N (out), P8 ND_D3/SD_D3 (out), P9 ND_D2/SD_D2 (out), P10 ND_D1/SD_D1 (out), P11 DSR_N (io), P12 RXD (io), R6 RXD2 (in), R7 ND_D5/bt_aux (out), R8 ND_CS_N (out), R9 ND_WP/SD_WP (out), R10 ND_D0/SD_D0 (out), R11 DCD_N (io), R12 RIN (io), T6 I2C_SD (out), T7 ND_D6/bt_wact (out), T8 ND_CLE/SD_card_detect, T9 ND_WE_N (out), T10 ND_ALE/SD_CMD (out), T11 TXD (out), T12 CTS_N (io), U6 I2C_SCLK (io), U7 ND_D7/bt_ant (out), U8 ND_D4/bt_stat (out), U9 ND_RE_N (out), U10 ND_RB_N/SD_CLK (out), U11 DTR_N (out)
part D pins: A8 APCK_RFCKOP (out), A9 PCIE_RXN (out), A10 PCIE_TXP, A11 PCIE_RFCKP (out), B8 APCK_RFCKON (out), B9 PCIE_RXP (out), B10 PCIE_TXN, B11 PCIE_RFCKN (out), C5 GND, C9 PCIE_REXT, C10 PERST_N, C16 UPHY0_PADP (io), C17 UPHY0_PADM (io), D16 UPHY1_PADM (io), D17 UPHY1_PADP (io), E3 GND, E4 GND, E8 PCIE_V12A (out), E12 UPHY0_V12D (in), E13 UPHY0_V12D (in), E14 UPHY1_V33A (in), E15 UPHY1_V33A (in), E16 UPHY0_VRES (io), E17 UPHY1_VRES (io), H6 GND (power), H7 GND (power), H8 GND (power), H9 GND (power), H10 GND (power), H11 GND (power), H12 GND (power), R17 GND, U12 GND
part E pins: F1 EPHY_LED3_N_JTCLK (out), F2 EPHY_LED2_N_JTMS (out), F4 EPHY_LED1_N_JTDI (out), F14 GE2_RXD0 (in), F15 GE2_RXD1 (in), F16 GE1_RXD2 (in), F17 GE1_RXD3 (in), G3 EPHY_LED0_N_JTDO (out), G4 EPHY_LED4_N_JTRST_N (out), G14 GE2_RXD2 (in), G15 GE1_RXDV (in), G16 GE1_RXD0 (in), G17 GE1_RXD1 (in), H13 GE_RGMII_IO_V33D (in), H14 GE2_RXD3 (in), H15 GE1_RXCLK (io), H16 GE1_RXCLK (io), H17 GE1_RXDV (in), J13 GE_RGMII_IO_V33D (in), J14 GE2_TXD1 (out), J15 GE2_TXD0 (out), J16 GE1_TXD0 (out), J17 GE1_TXD1 (out), K14 GE2_TXD3 (out), K15 GE2_TXD2 (out), K16 GE1_TXD2 (out), K17 GE1_TXD3 (out), L14 GE2_TXEN (out), L15 GE2_TXCLK (io), L16 GE1_TXCLK (io), L17 GE1_TXEN (out), M13 EPHY_V12A (in), M14 MDIO (io), M15 MDC (out), M17 EPHY_RES_VBG (io), N12 EPHY_V12A (in), N13 EPHY_V33A (in), N14 MDI_TN_P0 (out), N15 MDI_TP_P0 (out), N16 MDI_RN_P0 (in), N17 MDI_RP_P0 (in), P13 EPHY_V33A (in), P14 MDI_RN_P1 (in), P15 MDI_TP_P2 (out), P16 MDI_TN_P4 (out), P17 MDI_TP_P4 (out), R13 EPHY_V33A (in), R14 MDI_RP_P1 (in), R15 MDI_TN_P2 (out), R16 MDI_RN_P4 (in), R17 MDI_RP_P4 (in), T14 MDI_TN_P1 (out), T15 MDI_RP_P2 (in), T16 MDI_TN_P3 (out), T17 MDI_RN_P3 (in), U14 MDI_TP_P1 (out), U15 MDI_RN_P2 (in), U16 MDI_TP_P3 (out), U17 MDI_RP_P3 (in)
part F pins: A5 BBPLL_V12A (in), A14 COMP (in), A15 UGATE (in), A16 DCDC_V33D (in), A17 VFB_DIG (in), B5 BBPLL_V12D (in), B14 FB (in), B15 LGATE (in), B16 EXT_LDO_DIG (out), C11 APCK_VCCA (in), C13 EXT_LDO_DDR (out), C15 DCDC_V33A (in), D12 PCIE_V33A (in), D13 VFB_DDR (in), E6 SOC_IO_V33D_0 (in), E7 SOC_CO_V12D_0 (in), F5 SOC_IO_V33D_1 (in), G5 SOC_CO_V12D_1 (in), N7 SOC_CO_V12D_2 (in), N8 SOC_CO_V12D_2 (in), N10 SOC_IO_V33D_2 (in), N11 SOC_IO_V33D_2 (in)

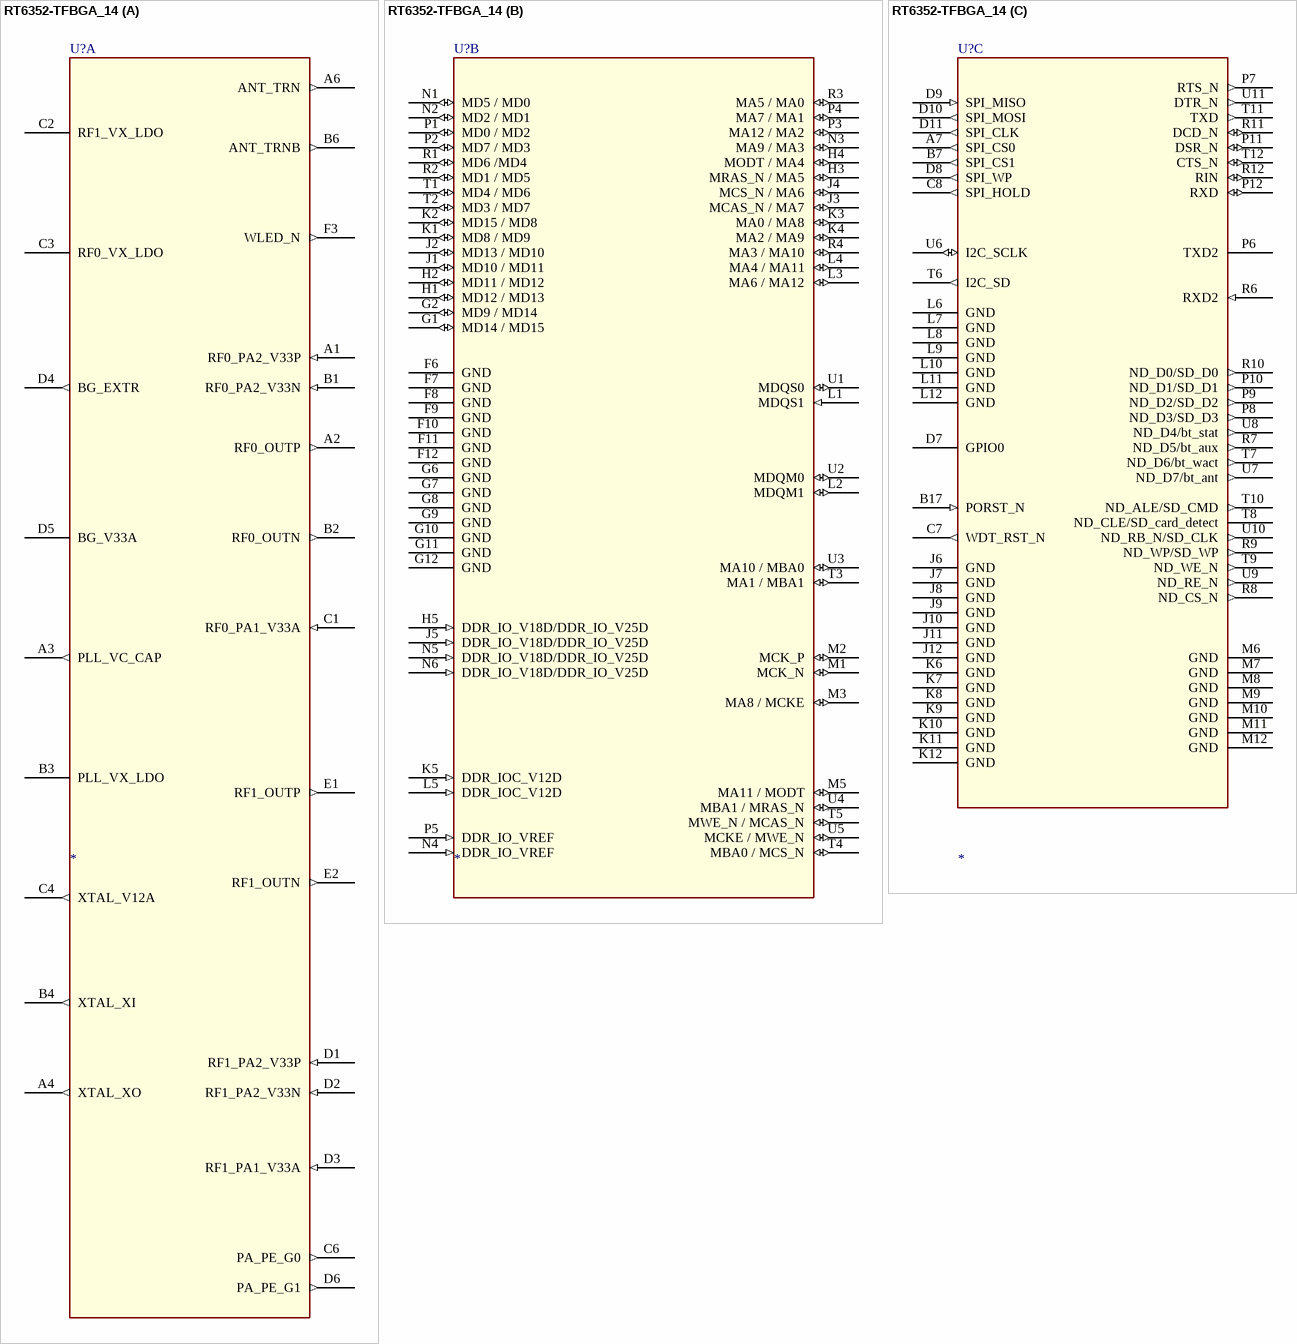
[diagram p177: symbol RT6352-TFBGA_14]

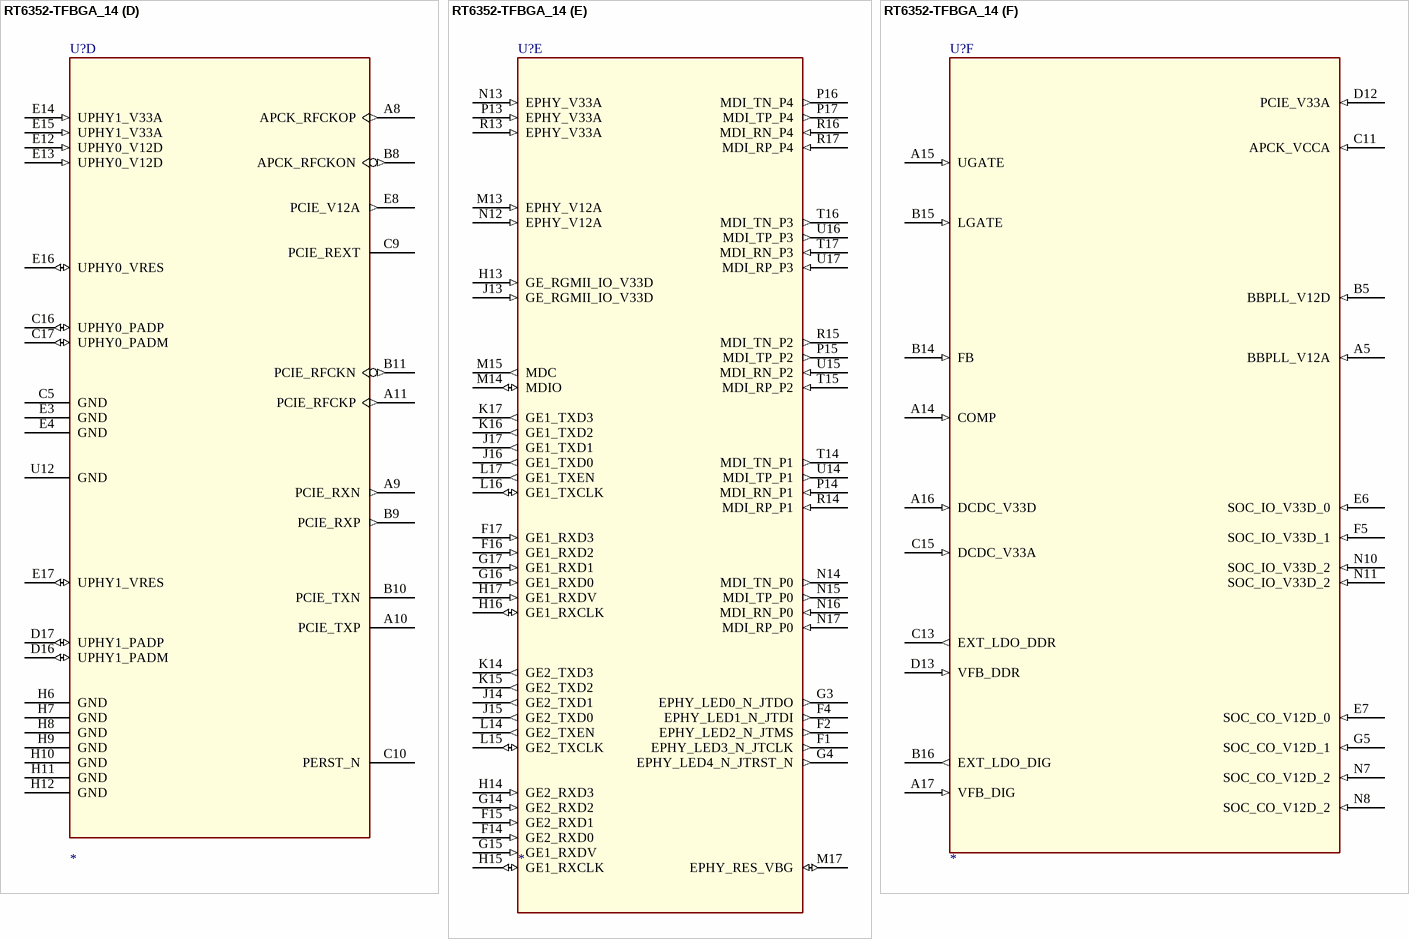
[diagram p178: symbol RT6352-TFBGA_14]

## RT6352-TFBGA_14
designator U?
footprint RT6352/BGA289/P0.65/12X12
part A pins: A1 RF0_PA2_V33P (in), A2 RF0_OUTP (out), A3 PLL_VC_CAP (out), A4 XTAL_XO (out), A6 ANT_TRN (out), B1 RF0_PA2_V33N (in), B2 RF0_OUTN (out), B3 PLL_VX_LDO, B4 XTAL_XI (out), B6 ANT_TRNB (out), C1 RF0_PA1_V33A (in), C2 RF1_VX_LDO, C3 RF0_VX_LDO, C4 XTAL_V12A (out), C6 PA_PE_G0 (out), D1 RF1_PA2_V33P (in), D2 RF1_PA2_V33N (in), D3 RF1_PA1_V33A (in), D4 BG_EXTR (out), D5 BG_V33A, D6 PA_PE_G1 (out), E1 RF1_OUTP (out), E2 RF1_OUTN (out), F3 WLED_N (out)
part B pins: F6 GND (power), F7 GND (power), F8 GND (power), F9 GND (power), F10 GND (power), F11 GND (power), F12 GND (power), G1 MD14 / MD15 (io), G2 MD9 / MD14 (io), G6 GND (power), G7 GND (power), G8 GND (power), G9 GND (power), G10 GND (power), G11 GND (power), G12 GND (power), H1 MD12 / MD13 (io), H2 MD11 / MD12 (io), H3 MRAS_N / MA5 (io), H4 MODT / MA4 (io), H5 DDR_IO_V18D/DDR_IO_V25D (in), J1 MD10 / MD11 (io), J2 MD13 / MD10 (io), J3 MCAS_N / MA7 (io), J4 MCS_N / MA6 (io), J5 DDR_IO_V18D/DDR_IO_V25D (in), K1 MD8 / MD9 (io), K2 MD15 / MD8 (io), K3 MA0 / MA8 (io), K4 MA2 / MA9 (io), K5 DDR_IOC_V12D (in), L1 MDQS1 (in), L2 MDQM1 (io), L3 MA6 / MA12 (io), L4 MA4 / MA11 (io), L5 DDR_IOC_V12D (in), M1 MCK_N (io), M2 MCK_P (io), M3 MA8 / MCKE (io), M5 MA11 / MODT (io), N1 MD5 / MD0 (io), N2 MD2 / MD1 (io), N3 MA9 / MA3 (io), N4 DDR_IO_VREF (in), N5 DDR_IO_V18D/DDR_IO_V25D (in), N6 DDR_IO_V18D/DDR_IO_V25D (in), P1 MD0 / MD2 (io), P2 MD7 / MD3 (io), P3 MA12 / MA2 (io), P4 MA7 / MA1 (io), P5 DDR_IO_VREF (in), R1 MD6 /MD4 (io), R2 MD1 / MD5 (io), R3 MA5 / MA0 (io), R4 MA3 / MA10 (io), T1 MD4 / MD6 (io), T2 MD3 / MD7 (io), T3 MA1 / MBA1 (io), T4 MBA0 / MCS_N (io), T5 MWE_N / MCAS_N (io), U1 MDQS0 (io), U2 MDQM0 (io), U3 MA10 / MBA0 (io), U4 MBA1 / MRAS_N (io), U5 MCKE / MWE_N (io)
part C pins: A7 SPI_CS0 (out), B7 SPI_CS1 (out), B17 PORST_N (in), C7 WDT_RST_N (out), C8 SPI_HOLD (out), D7 GPIO0, D8 SPI_WP (out), D9 SPI_MISO (in), D10 SPI_MOSI (out), D11 SPI_CLK (out), J6 GND (power), J7 GND (power), J8 GND (power), J9 GND (power), J10 GND (power), J11 GND (power), J12 GND (power), K6 GND (power), K7 GND (power), K8 GND (power), K9 GND (power), K10 GND (power), K11 GND (power), K12 GND (power), L6 GND (power), L7 GND (power), L8 GND (power), L9 GND (power), L10 GND (power), L11 GND (power), L12 GND (power), M6 GND (power), M7 GND (power), M8 GND (power), M9 GND (power), M10 GND (power), M11 GND (power), M12 GND (power), P6 TXD2, P7 RTS_N (out), P8 ND_D3/SD_D3 (out), P9 ND_D2/SD_D2 (out), P10 ND_D1/SD_D1 (out), P11 DSR_N (io), P12 RXD (io), R6 RXD2 (in), R7 ND_D5/bt_aux (out), R8 ND_CS_N (out), R9 ND_WP/SD_WP (out), R10 ND_D0/SD_D0 (out), R11 DCD_N (io), R12 RIN (io), T6 I2C_SD (out), T7 ND_D6/bt_wact (out), T8 ND_CLE/SD_card_detect, T9 ND_WE_N (out), T10 ND_ALE/SD_CMD (out), T11 TXD (out), T12 CTS_N (io), U6 I2C_SCLK (io), U7 ND_D7/bt_ant (out), U8 ND_D4/bt_stat (out), U9 ND_RE_N (out), U10 ND_RB_N/SD_CLK (out), U11 DTR_N (out)
part D pins: A8 APCK_RFCKOP (out), A9 PCIE_RXN (out), A10 PCIE_TXP, A11 PCIE_RFCKP (out), B8 APCK_RFCKON (out), B9 PCIE_RXP (out), B10 PCIE_TXN, B11 PCIE_RFCKN (out), C5 GND, C9 PCIE_REXT, C10 PERST_N, C16 UPHY0_PADP (io), C17 UPHY0_PADM (io), D16 UPHY1_PADM (io), D17 UPHY1_PADP (io), E3 GND, E4 GND, E8 PCIE_V12A (out), E12 UPHY0_V12D (in), E13 UPHY0_V12D (in), E14 UPHY1_V33A (in), E15 UPHY1_V33A (in), E16 UPHY0_VRES (io), E17 UPHY1_VRES (io), H6 GND (power), H7 GND (power), H8 GND (power), H9 GND (power), H10 GND (power), H11 GND (power), H12 GND (power), U12 GND
part E pins: F1 EPHY_LED3_N_JTCLK (out), F2 EPHY_LED2_N_JTMS (out), F4 EPHY_LED1_N_JTDI (out), F14 GE2_RXD0 (in), F15 GE2_RXD1 (in), F16 GE1_RXD2 (in), F17 GE1_RXD3 (in), G3 EPHY_LED0_N_JTDO (out), G4 EPHY_LED4_N_JTRST_N (out), G14 GE2_RXD2 (in), G15 GE1_RXDV (in), G16 GE1_RXD0 (in), G17 GE1_RXD1 (in), H13 GE_RGMII_IO_V33D (in), H14 GE2_RXD3 (in), H15 GE1_RXCLK (io), H16 GE1_RXCLK (io), H17 GE1_RXDV (in), J13 GE_RGMII_IO_V33D (in), J14 GE2_TXD1 (out), J15 GE2_TXD0 (out), J16 GE1_TXD0 (out), J17 GE1_TXD1 (out), K14 GE2_TXD3 (out), K15 GE2_TXD2 (out), K16 GE1_TXD2 (out), K17 GE1_TXD3 (out), L14 GE2_TXEN (out), L15 GE2_TXCLK (io), L16 GE1_TXCLK (io), L17 GE1_TXEN (out), M13 EPHY_V12A (in), M14 MDIO (io), M15 MDC (out), M17 EPHY_RES_VBG (io), N12 EPHY_V12A (in), N13 EPHY_V33A (in), N14 MDI_TN_P0 (out), N15 MDI_TP_P0 (out), N16 MDI_RN_P0 (in), N17 MDI_RP_P0 (in), P13 EPHY_V33A (in), P14 MDI_RN_P1 (in), P15 MDI_TP_P2 (out), P16 MDI_TN_P4 (out), P17 MDI_TP_P4 (out), R13 EPHY_V33A (in), R14 MDI_RP_P1 (in), R15 MDI_TN_P2 (out), R16 MDI_RN_P4 (in), R17 MDI_RP_P4 (in), T14 MDI_TN_P1 (out), T15 MDI_RP_P2 (in), T16 MDI_TN_P3 (out), T17 MDI_RN_P3 (in), U14 MDI_TP_P1 (out), U15 MDI_RN_P2 (in), U16 MDI_TP_P3 (out), U17 MDI_RP_P3 (in)
part F pins: A5 BBPLL_V12A (in), A14 COMP (in), A15 UGATE (in), A16 DCDC_V33D (in), A17 VFB_DIG (in), B5 BBPLL_V12D (in), B14 FB (in), B15 LGATE (in), B16 EXT_LDO_DIG (out), C11 APCK_VCCA (in), C13 EXT_LDO_DDR (out), C15 DCDC_V33A (in), D12 PCIE_V33A (in), D13 VFB_DDR (in), E6 SOC_IO_V33D_0 (in), E7 SOC_CO_V12D_0 (in), F5 SOC_IO_V33D_1 (in), G5 SOC_CO_V12D_1 (in), N7 SOC_CO_V12D_2 (in), N8 SOC_CO_V12D_2 (in), N10 SOC_IO_V33D_2 (in), N11 SOC_IO_V33D_2 (in)

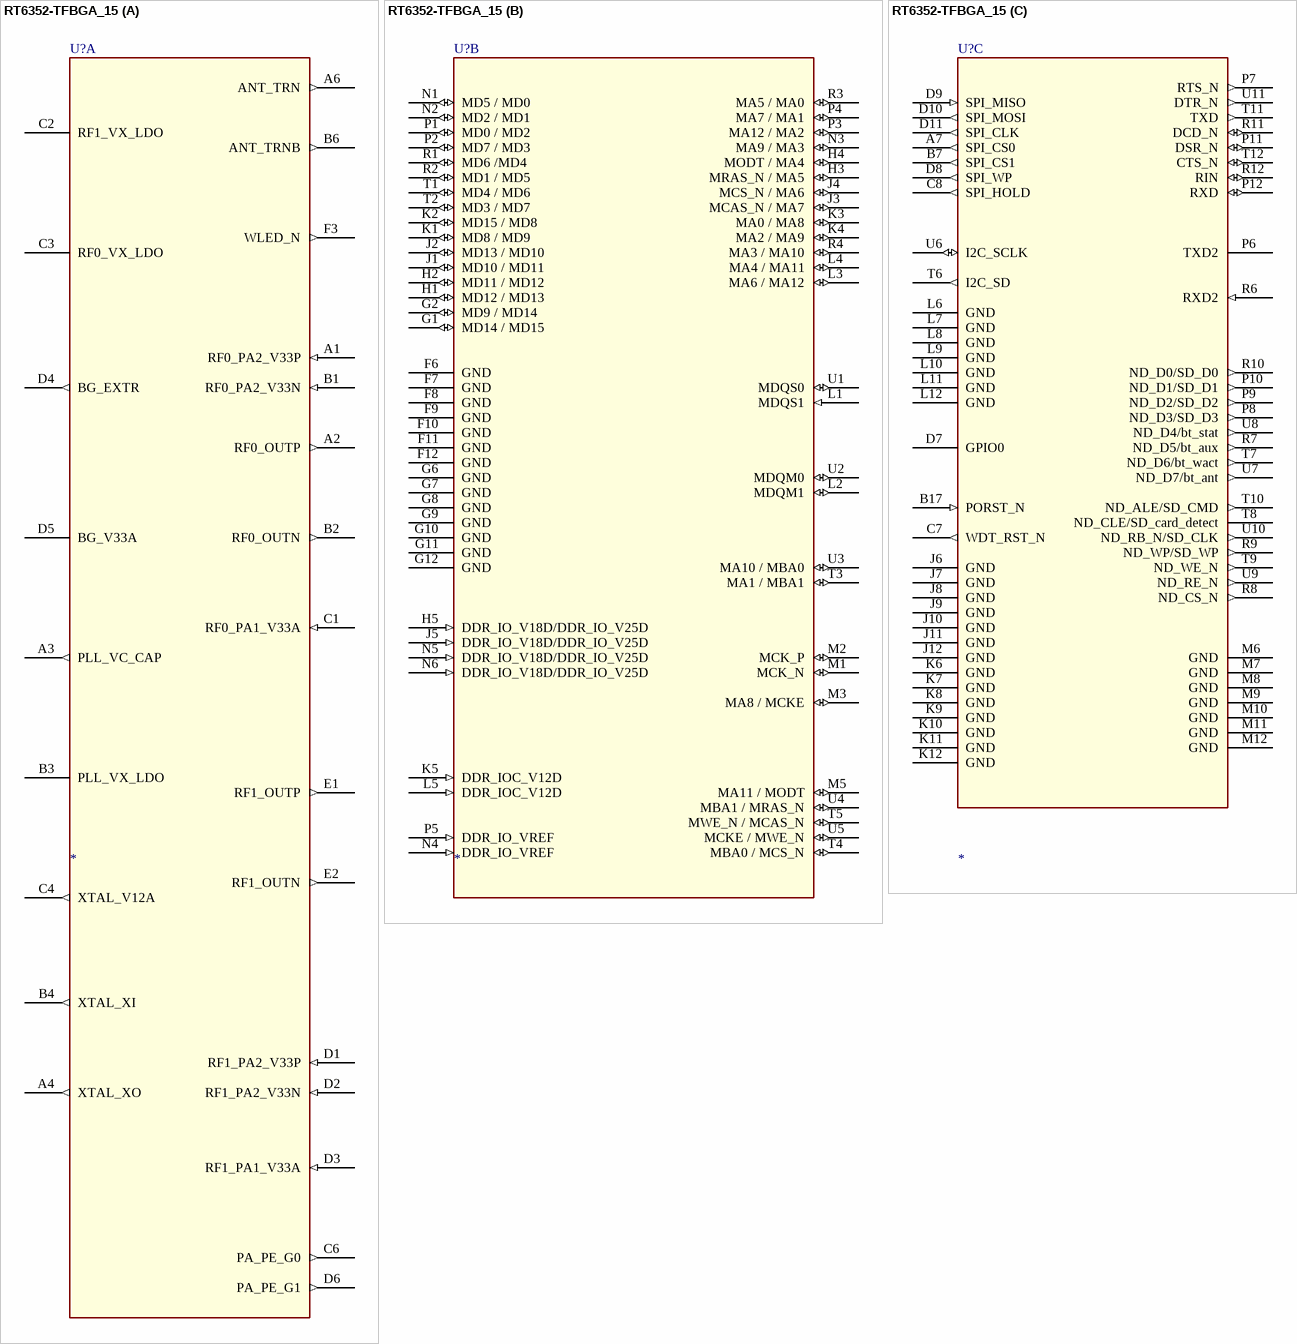
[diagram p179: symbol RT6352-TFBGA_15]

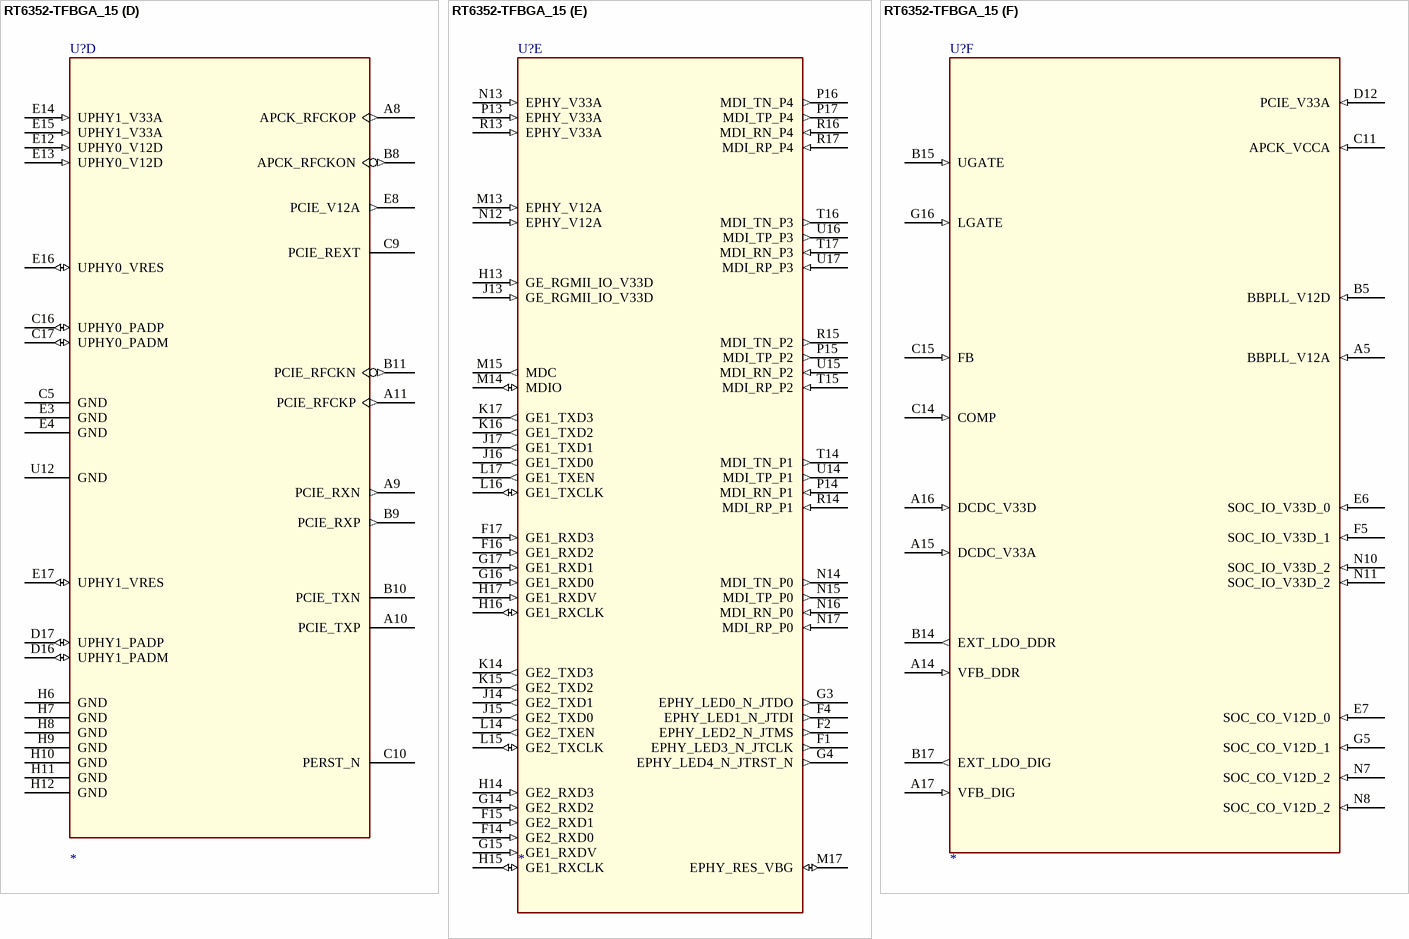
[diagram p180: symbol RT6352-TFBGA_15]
